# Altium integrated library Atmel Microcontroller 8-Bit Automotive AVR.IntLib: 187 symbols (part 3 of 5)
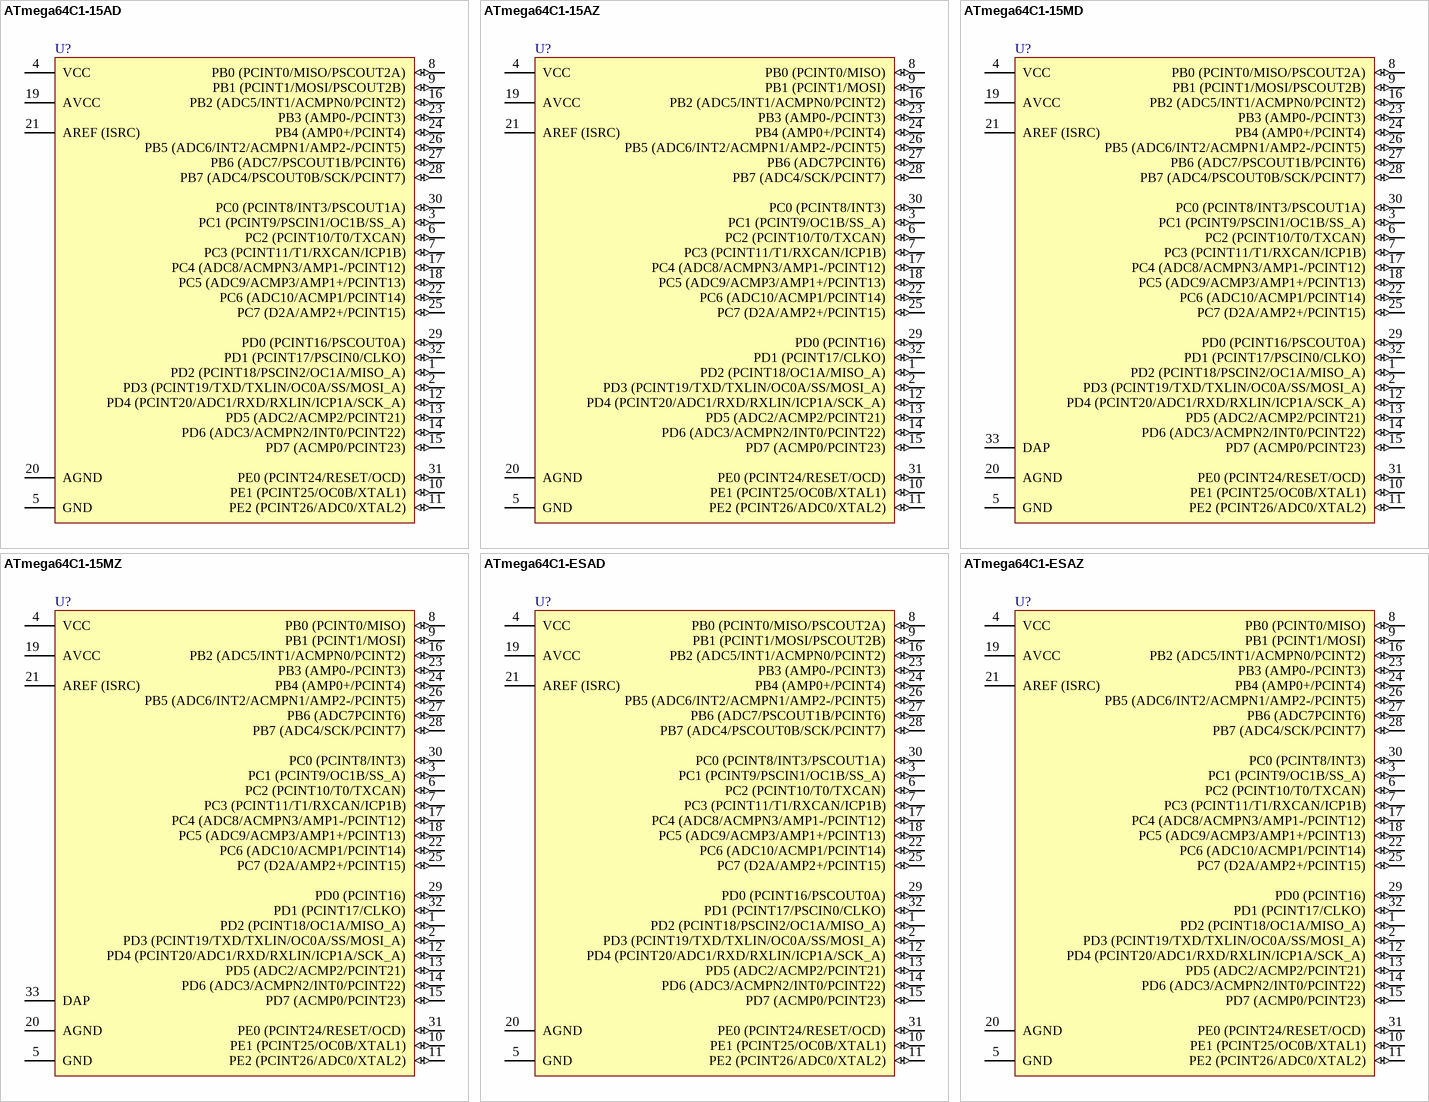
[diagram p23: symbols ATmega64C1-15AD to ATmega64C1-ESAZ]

## ATmega64C1-ESAZ
designator U?
8-bit Automotive AVR Microcontroller, 64KB Flash, 2KB EEPROM, 4KB SRAM, Engineering Sample, 32-Pin TQFP
footprint 32MA_N (Thin QFP, 32-Leads, Body 7x7mm, Pitch 0.8mm, IPC Medium Density)
footprint 32MA_L (Thin QFP, 32-Leads, Body 7x7mm, Pitch 0.8mm, IPC High Density)
footprint 32MA_M (Thin QFP, 32-Leads, Body 7x7mm, Pitch 0.8mm, IPC Low Density)
pins: 1 PD2 (PCINT18/OC1A/MISO_A) (io), 2 PD3 (PCINT19/TXD/TXLIN/OC0A/SS/MOSI_A) (io), 3 PC1 (PCINT9/OC1B/SS_A) (io), 4 VCC (power), 5 GND (power), 6 PC2 (PCINT10/T0/TXCAN) (io), 7 PC3 (PCINT11/T1/RXCAN/ICP1B) (io), 8 PB0 (PCINT0/MISO) (io), 9 PB1 (PCINT1/MOSI) (io), 10 PE1 (PCINT25/OC0B/XTAL1) (io), 11 PE2 (PCINT26/ADC0/XTAL2) (io), 12 PD4 (PCINT20/ADC1/RXD/RXLIN/ICP1A/SCK_A) (io), 13 PD5 (ADC2/ACMP2/PCINT21) (io), 14 PD6 (ADC3/ACMPN2/INT0/PCINT22) (io), 15 PD7 (ACMP0/PCINT23) (io), 16 PB2 (ADC5/INT1/ACMPN0/PCINT2) (io), 17 PC4 (ADC8/ACMPN3/AMP1-/PCINT12) (io), 18 PC5 (ADC9/ACMP3/AMP1+/PCINT13) (io), 19 AVCC (power), 20 AGND (power), 21 AREF (ISRC) (power), 22 PC6 (ADC10/ACMP1/PCINT14) (io), 23 PB3 (AMP0-/PCINT3) (io), 24 PB4 (AMP0+/PCINT4) (io), 25 PC7 (D2A/AMP2+/PCINT15) (io), 26 PB5 (ADC6/INT2/ACMPN1/AMP2-/PCINT5) (io), 27 PB6 (ADC7PCINT6) (io), 28 PB7 (ADC4/SCK/PCINT7) (io), 29 PD0 (PCINT16) (io), 30 PC0 (PCINT8/INT3) (io), 31 PE0 (PCINT24/RESET/OCD) (io), 32 PD1 (PCINT17/CLKO) (io)

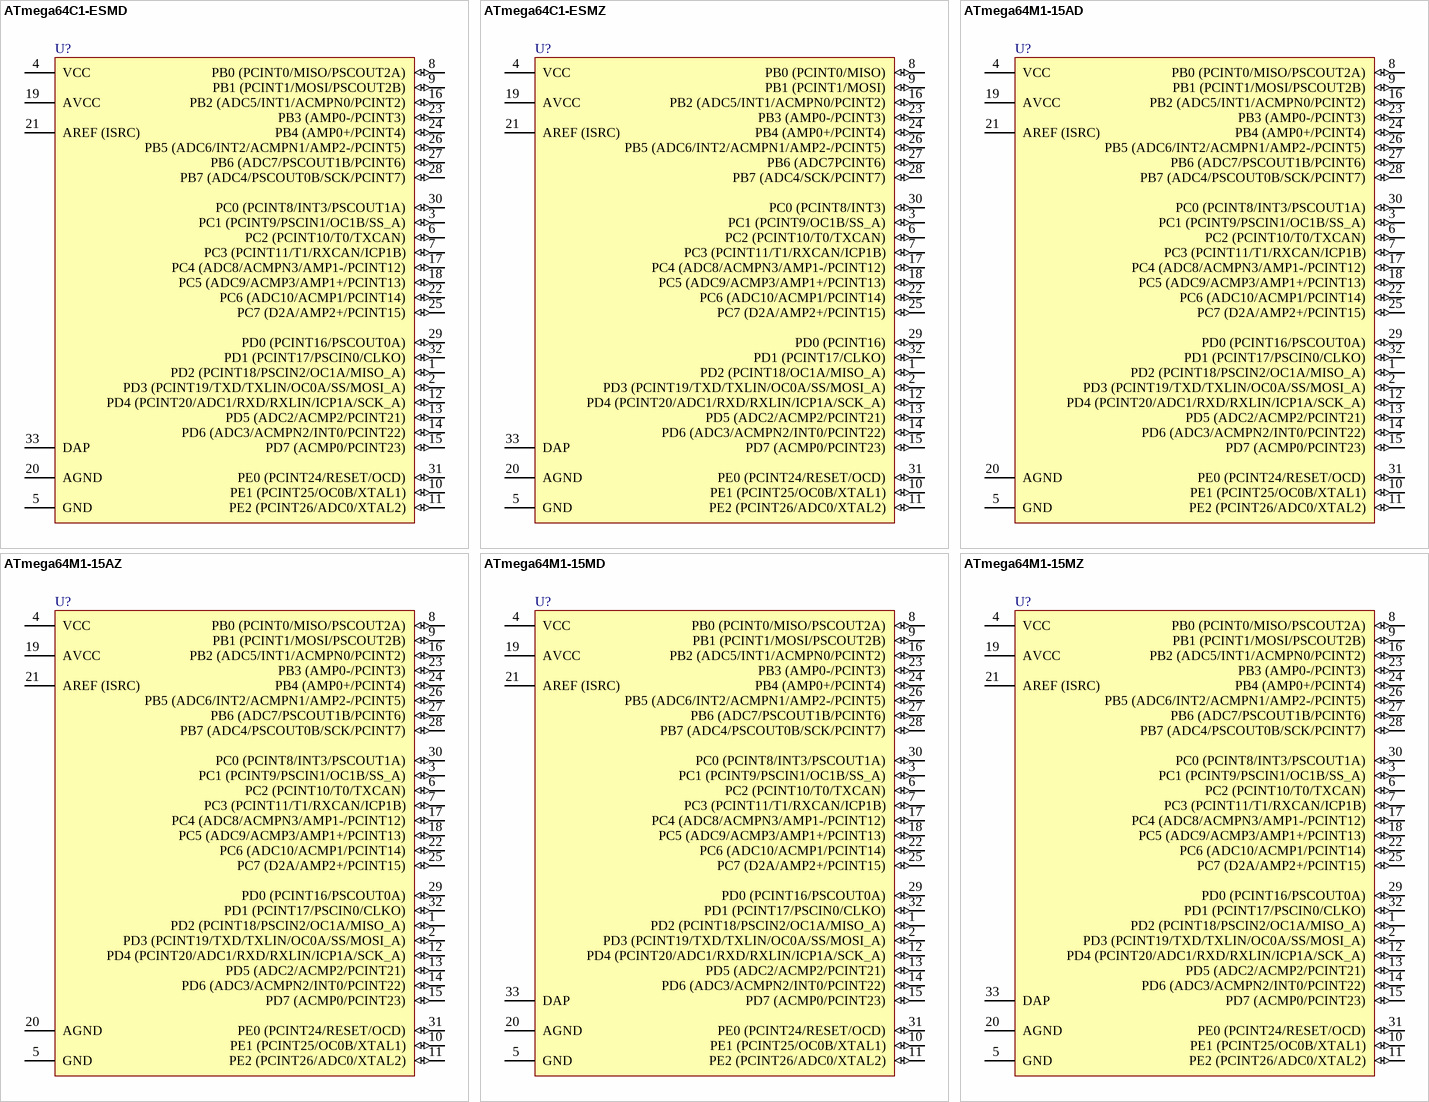
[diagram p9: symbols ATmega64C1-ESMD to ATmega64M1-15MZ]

## ATmega64C1-ESMD
designator U?
8-bit Automotive AVR Microcontroller, 64KB Flash, 2KB EEPROM, 4KB SRAM, Engineering Sample, 32-Pin VQFN
footprint 32PV_N (QFN, 32-Leads, Body 7x7 mm, Pitch 0.65mm, IPC Medium Density)
footprint 32PV_L (QFN, 32-Leads, Body 7x7 mm, Pitch 0.65mm, IPC High Density)
footprint 32PV_M (QFN, 32-Leads, Body 7x7 mm, Pitch 0.65mm, IPC Low Density)
pins: 1 PD2 (PCINT18/PSCIN2/OC1A/MISO_A) (io), 2 PD3 (PCINT19/TXD/TXLIN/OC0A/SS/MOSI_A) (io), 3 PC1 (PCINT9/PSCIN1/OC1B/SS_A) (io), 4 VCC (power), 5 GND (power), 6 PC2 (PCINT10/T0/TXCAN) (io), 7 PC3 (PCINT11/T1/RXCAN/ICP1B) (io), 8 PB0 (PCINT0/MISO/PSCOUT2A) (io), 9 PB1 (PCINT1/MOSI/PSCOUT2B) (io), 10 PE1 (PCINT25/OC0B/XTAL1) (io), 11 PE2 (PCINT26/ADC0/XTAL2) (io), 12 PD4 (PCINT20/ADC1/RXD/RXLIN/ICP1A/SCK_A) (io), 13 PD5 (ADC2/ACMP2/PCINT21) (io), 14 PD6 (ADC3/ACMPN2/INT0/PCINT22) (io), 15 PD7 (ACMP0/PCINT23) (io), 16 PB2 (ADC5/INT1/ACMPN0/PCINT2) (io), 17 PC4 (ADC8/ACMPN3/AMP1-/PCINT12) (io), 18 PC5 (ADC9/ACMP3/AMP1+/PCINT13) (io), 19 AVCC (power), 20 AGND (power), 21 AREF (ISRC) (power), 22 PC6 (ADC10/ACMP1/PCINT14) (io), 23 PB3 (AMP0-/PCINT3) (io), 24 PB4 (AMP0+/PCINT4) (io), 25 PC7 (D2A/AMP2+/PCINT15) (io), 26 PB5 (ADC6/INT2/ACMPN1/AMP2-/PCINT5) (io), 27 PB6 (ADC7/PSCOUT1B/PCINT6) (io), 28 PB7 (ADC4/PSCOUT0B/SCK/PCINT7) (io), 29 PD0 (PCINT16/PSCOUT0A) (io), 30 PC0 (PCINT8/INT3/PSCOUT1A) (io), 31 PE0 (PCINT24/RESET/OCD) (io), 32 PD1 (PCINT17/PSCIN0/CLKO) (io), 33 DAP (power)

## ATmega64C1-ESMZ
designator U?
8-bit Automotive AVR Microcontroller, 64KB Flash, 2KB EEPROM, 4KB SRAM, Engineering Sample, 32-Pin VQFN
footprint 32PV_N (QFN, 32-Leads, Body 7x7 mm, Pitch 0.65mm, IPC Medium Density)
footprint 32PV_L (QFN, 32-Leads, Body 7x7 mm, Pitch 0.65mm, IPC High Density)
footprint 32PV_M (QFN, 32-Leads, Body 7x7 mm, Pitch 0.65mm, IPC Low Density)
pins: 1 PD2 (PCINT18/OC1A/MISO_A) (io), 2 PD3 (PCINT19/TXD/TXLIN/OC0A/SS/MOSI_A) (io), 3 PC1 (PCINT9/OC1B/SS_A) (io), 4 VCC (power), 5 GND (power), 6 PC2 (PCINT10/T0/TXCAN) (io), 7 PC3 (PCINT11/T1/RXCAN/ICP1B) (io), 8 PB0 (PCINT0/MISO) (io), 9 PB1 (PCINT1/MOSI) (io), 10 PE1 (PCINT25/OC0B/XTAL1) (io), 11 PE2 (PCINT26/ADC0/XTAL2) (io), 12 PD4 (PCINT20/ADC1/RXD/RXLIN/ICP1A/SCK_A) (io), 13 PD5 (ADC2/ACMP2/PCINT21) (io), 14 PD6 (ADC3/ACMPN2/INT0/PCINT22) (io), 15 PD7 (ACMP0/PCINT23) (io), 16 PB2 (ADC5/INT1/ACMPN0/PCINT2) (io), 17 PC4 (ADC8/ACMPN3/AMP1-/PCINT12) (io), 18 PC5 (ADC9/ACMP3/AMP1+/PCINT13) (io), 19 AVCC (power), 20 AGND (power), 21 AREF (ISRC) (power), 22 PC6 (ADC10/ACMP1/PCINT14) (io), 23 PB3 (AMP0-/PCINT3) (io), 24 PB4 (AMP0+/PCINT4) (io), 25 PC7 (D2A/AMP2+/PCINT15) (io), 26 PB5 (ADC6/INT2/ACMPN1/AMP2-/PCINT5) (io), 27 PB6 (ADC7PCINT6) (io), 28 PB7 (ADC4/SCK/PCINT7) (io), 29 PD0 (PCINT16) (io), 30 PC0 (PCINT8/INT3) (io), 31 PE0 (PCINT24/RESET/OCD) (io), 32 PD1 (PCINT17/CLKO) (io), 33 DAP (power)

## ATmega64M1-15AD
designator U?
8-bit Automotive AVR Microcontroller, 64KB Flash, 2KB EEPROM, 4KB SRAM, Extended Grade (-40°C to +150°C), 32-Pin TQFP
footprint 32MA_N (Thin QFP, 32-Leads, Body 7x7mm, Pitch 0.8mm, IPC Medium Density)
footprint 32MA_L (Thin QFP, 32-Leads, Body 7x7mm, Pitch 0.8mm, IPC High Density)
footprint 32MA_M (Thin QFP, 32-Leads, Body 7x7mm, Pitch 0.8mm, IPC Low Density)
pins: 1 PD2 (PCINT18/PSCIN2/OC1A/MISO_A) (io), 2 PD3 (PCINT19/TXD/TXLIN/OC0A/SS/MOSI_A) (io), 3 PC1 (PCINT9/PSCIN1/OC1B/SS_A) (io), 4 VCC (power), 5 GND (power), 6 PC2 (PCINT10/T0/TXCAN) (io), 7 PC3 (PCINT11/T1/RXCAN/ICP1B) (io), 8 PB0 (PCINT0/MISO/PSCOUT2A) (io), 9 PB1 (PCINT1/MOSI/PSCOUT2B) (io), 10 PE1 (PCINT25/OC0B/XTAL1) (io), 11 PE2 (PCINT26/ADC0/XTAL2) (io), 12 PD4 (PCINT20/ADC1/RXD/RXLIN/ICP1A/SCK_A) (io), 13 PD5 (ADC2/ACMP2/PCINT21) (io), 14 PD6 (ADC3/ACMPN2/INT0/PCINT22) (io), 15 PD7 (ACMP0/PCINT23) (io), 16 PB2 (ADC5/INT1/ACMPN0/PCINT2) (io), 17 PC4 (ADC8/ACMPN3/AMP1-/PCINT12) (io), 18 PC5 (ADC9/ACMP3/AMP1+/PCINT13) (io), 19 AVCC (power), 20 AGND (power), 21 AREF (ISRC) (power), 22 PC6 (ADC10/ACMP1/PCINT14) (io), 23 PB3 (AMP0-/PCINT3) (io), 24 PB4 (AMP0+/PCINT4) (io), 25 PC7 (D2A/AMP2+/PCINT15) (io), 26 PB5 (ADC6/INT2/ACMPN1/AMP2-/PCINT5) (io), 27 PB6 (ADC7/PSCOUT1B/PCINT6) (io), 28 PB7 (ADC4/PSCOUT0B/SCK/PCINT7) (io), 29 PD0 (PCINT16/PSCOUT0A) (io), 30 PC0 (PCINT8/INT3/PSCOUT1A) (io), 31 PE0 (PCINT24/RESET/OCD) (io), 32 PD1 (PCINT17/PSCIN0/CLKO) (io)

## ATmega64M1-15AZ
designator U?
8-bit Automotive AVR Microcontroller, 64KB Flash, 2KB EEPROM, 4KB SRAM, PSC, Automotive Grade (-40°C to +125°C), 32-Pin TQFP
footprint 32MA_N (Thin QFP, 32-Leads, Body 7x7mm, Pitch 0.8mm, IPC Medium Density)
footprint 32MA_L (Thin QFP, 32-Leads, Body 7x7mm, Pitch 0.8mm, IPC High Density)
footprint 32MA_M (Thin QFP, 32-Leads, Body 7x7mm, Pitch 0.8mm, IPC Low Density)
pins: 1 PD2 (PCINT18/PSCIN2/OC1A/MISO_A) (io), 2 PD3 (PCINT19/TXD/TXLIN/OC0A/SS/MOSI_A) (io), 3 PC1 (PCINT9/PSCIN1/OC1B/SS_A) (io), 4 VCC (power), 5 GND (power), 6 PC2 (PCINT10/T0/TXCAN) (io), 7 PC3 (PCINT11/T1/RXCAN/ICP1B) (io), 8 PB0 (PCINT0/MISO/PSCOUT2A) (io), 9 PB1 (PCINT1/MOSI/PSCOUT2B) (io), 10 PE1 (PCINT25/OC0B/XTAL1) (io), 11 PE2 (PCINT26/ADC0/XTAL2) (io), 12 PD4 (PCINT20/ADC1/RXD/RXLIN/ICP1A/SCK_A) (io), 13 PD5 (ADC2/ACMP2/PCINT21) (io), 14 PD6 (ADC3/ACMPN2/INT0/PCINT22) (io), 15 PD7 (ACMP0/PCINT23) (io), 16 PB2 (ADC5/INT1/ACMPN0/PCINT2) (io), 17 PC4 (ADC8/ACMPN3/AMP1-/PCINT12) (io), 18 PC5 (ADC9/ACMP3/AMP1+/PCINT13) (io), 19 AVCC (power), 20 AGND (power), 21 AREF (ISRC) (power), 22 PC6 (ADC10/ACMP1/PCINT14) (io), 23 PB3 (AMP0-/PCINT3) (io), 24 PB4 (AMP0+/PCINT4) (io), 25 PC7 (D2A/AMP2+/PCINT15) (io), 26 PB5 (ADC6/INT2/ACMPN1/AMP2-/PCINT5) (io), 27 PB6 (ADC7/PSCOUT1B/PCINT6) (io), 28 PB7 (ADC4/PSCOUT0B/SCK/PCINT7) (io), 29 PD0 (PCINT16/PSCOUT0A) (io), 30 PC0 (PCINT8/INT3/PSCOUT1A) (io), 31 PE0 (PCINT24/RESET/OCD) (io), 32 PD1 (PCINT17/PSCIN0/CLKO) (io)

## ATmega64M1-15MD
designator U?
8-bit Automotive AVR Microcontroller, 64KB Flash, 2KB EEPROM, 4KB SRAM, Extended Grade (-40°C to +150°C), 32-Pin VQFN
footprint 32PV_N (QFN, 32-Leads, Body 7x7 mm, Pitch 0.65mm, IPC Medium Density)
footprint 32PV_L (QFN, 32-Leads, Body 7x7 mm, Pitch 0.65mm, IPC High Density)
footprint 32PV_M (QFN, 32-Leads, Body 7x7 mm, Pitch 0.65mm, IPC Low Density)
pins: 1 PD2 (PCINT18/PSCIN2/OC1A/MISO_A) (io), 2 PD3 (PCINT19/TXD/TXLIN/OC0A/SS/MOSI_A) (io), 3 PC1 (PCINT9/PSCIN1/OC1B/SS_A) (io), 4 VCC (power), 5 GND (power), 6 PC2 (PCINT10/T0/TXCAN) (io), 7 PC3 (PCINT11/T1/RXCAN/ICP1B) (io), 8 PB0 (PCINT0/MISO/PSCOUT2A) (io), 9 PB1 (PCINT1/MOSI/PSCOUT2B) (io), 10 PE1 (PCINT25/OC0B/XTAL1) (io), 11 PE2 (PCINT26/ADC0/XTAL2) (io), 12 PD4 (PCINT20/ADC1/RXD/RXLIN/ICP1A/SCK_A) (io), 13 PD5 (ADC2/ACMP2/PCINT21) (io), 14 PD6 (ADC3/ACMPN2/INT0/PCINT22) (io), 15 PD7 (ACMP0/PCINT23) (io), 16 PB2 (ADC5/INT1/ACMPN0/PCINT2) (io), 17 PC4 (ADC8/ACMPN3/AMP1-/PCINT12) (io), 18 PC5 (ADC9/ACMP3/AMP1+/PCINT13) (io), 19 AVCC (power), 20 AGND (power), 21 AREF (ISRC) (power), 22 PC6 (ADC10/ACMP1/PCINT14) (io), 23 PB3 (AMP0-/PCINT3) (io), 24 PB4 (AMP0+/PCINT4) (io), 25 PC7 (D2A/AMP2+/PCINT15) (io), 26 PB5 (ADC6/INT2/ACMPN1/AMP2-/PCINT5) (io), 27 PB6 (ADC7/PSCOUT1B/PCINT6) (io), 28 PB7 (ADC4/PSCOUT0B/SCK/PCINT7) (io), 29 PD0 (PCINT16/PSCOUT0A) (io), 30 PC0 (PCINT8/INT3/PSCOUT1A) (io), 31 PE0 (PCINT24/RESET/OCD) (io), 32 PD1 (PCINT17/PSCIN0/CLKO) (io), 33 DAP (power)

## ATmega64M1-15MZ
designator U?
8-bit Automotive AVR Microcontroller, 64KB Flash, 2KB EEPROM, 4KB SRAM, PSC, Automotive Grade (-40°C to +125°C), 32-Pin VQFN
footprint 32PV_N (QFN, 32-Leads, Body 7x7 mm, Pitch 0.65mm, IPC Medium Density)
footprint 32PV_L (QFN, 32-Leads, Body 7x7 mm, Pitch 0.65mm, IPC High Density)
footprint 32PV_M (QFN, 32-Leads, Body 7x7 mm, Pitch 0.65mm, IPC Low Density)
pins: 1 PD2 (PCINT18/PSCIN2/OC1A/MISO_A) (io), 2 PD3 (PCINT19/TXD/TXLIN/OC0A/SS/MOSI_A) (io), 3 PC1 (PCINT9/PSCIN1/OC1B/SS_A) (io), 4 VCC (power), 5 GND (power), 6 PC2 (PCINT10/T0/TXCAN) (io), 7 PC3 (PCINT11/T1/RXCAN/ICP1B) (io), 8 PB0 (PCINT0/MISO/PSCOUT2A) (io), 9 PB1 (PCINT1/MOSI/PSCOUT2B) (io), 10 PE1 (PCINT25/OC0B/XTAL1) (io), 11 PE2 (PCINT26/ADC0/XTAL2) (io), 12 PD4 (PCINT20/ADC1/RXD/RXLIN/ICP1A/SCK_A) (io), 13 PD5 (ADC2/ACMP2/PCINT21) (io), 14 PD6 (ADC3/ACMPN2/INT0/PCINT22) (io), 15 PD7 (ACMP0/PCINT23) (io), 16 PB2 (ADC5/INT1/ACMPN0/PCINT2) (io), 17 PC4 (ADC8/ACMPN3/AMP1-/PCINT12) (io), 18 PC5 (ADC9/ACMP3/AMP1+/PCINT13) (io), 19 AVCC (power), 20 AGND (power), 21 AREF (ISRC) (power), 22 PC6 (ADC10/ACMP1/PCINT14) (io), 23 PB3 (AMP0-/PCINT3) (io), 24 PB4 (AMP0+/PCINT4) (io), 25 PC7 (D2A/AMP2+/PCINT15) (io), 26 PB5 (ADC6/INT2/ACMPN1/AMP2-/PCINT5) (io), 27 PB6 (ADC7/PSCOUT1B/PCINT6) (io), 28 PB7 (ADC4/PSCOUT0B/SCK/PCINT7) (io), 29 PD0 (PCINT16/PSCOUT0A) (io), 30 PC0 (PCINT8/INT3/PSCOUT1A) (io), 31 PE0 (PCINT24/RESET/OCD) (io), 32 PD1 (PCINT17/PSCIN0/CLKO) (io), 33 DAP (power)

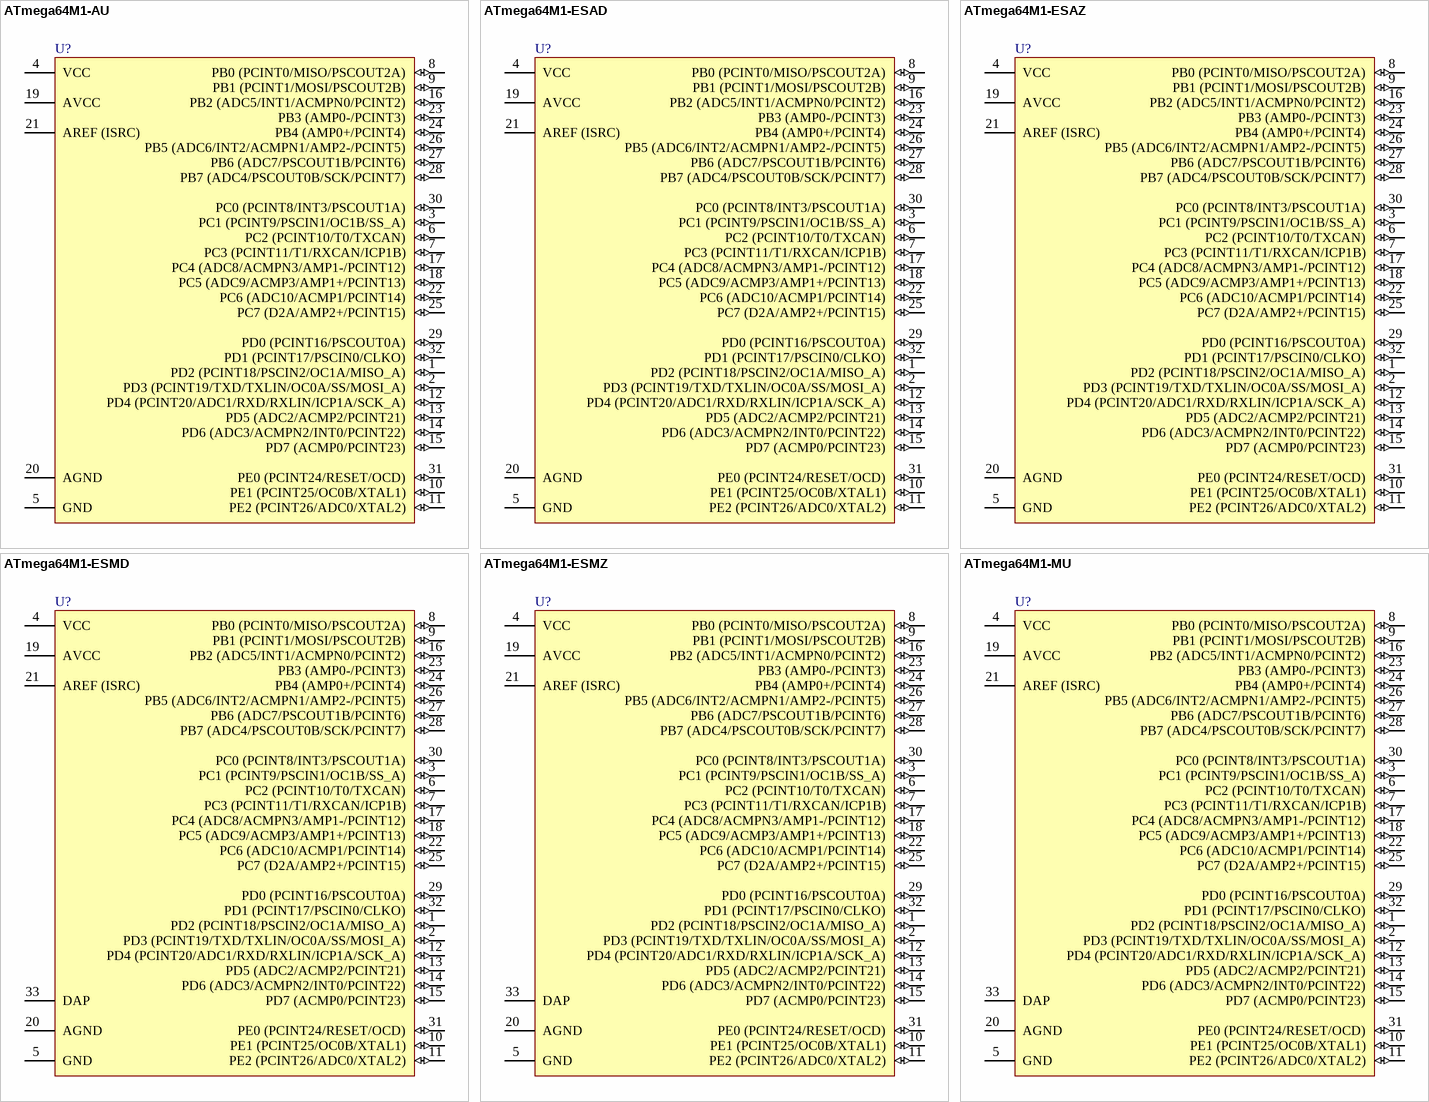
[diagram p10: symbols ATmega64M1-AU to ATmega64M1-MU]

## ATmega64M1-AU
designator U?
8-bit AVR Microcontroller, 64KB Flash, 2KB EEPROM, 4KB SRAM, Industrial Grade (-40° to +85°C), 32-Pin TQFP
footprint 32A_N (Thin QFP, 32-Leads, Body 7x7mm, Pitch 0.8mm, IPC Medium Density)
footprint 32A_L (Thin QFP, 32-Leads, Body 7x7mm, Pitch 0.8mm, IPC High Density)
footprint 32A_M (Thin QFP, 32-Leads, Body 7x7mm, Pitch 0.8mm, IPC Low Density)
pins: 1 PD2 (PCINT18/PSCIN2/OC1A/MISO_A) (io), 2 PD3 (PCINT19/TXD/TXLIN/OC0A/SS/MOSI_A) (io), 3 PC1 (PCINT9/PSCIN1/OC1B/SS_A) (io), 4 VCC (power), 5 GND (power), 6 PC2 (PCINT10/T0/TXCAN) (io), 7 PC3 (PCINT11/T1/RXCAN/ICP1B) (io), 8 PB0 (PCINT0/MISO/PSCOUT2A) (io), 9 PB1 (PCINT1/MOSI/PSCOUT2B) (io), 10 PE1 (PCINT25/OC0B/XTAL1) (io), 11 PE2 (PCINT26/ADC0/XTAL2) (io), 12 PD4 (PCINT20/ADC1/RXD/RXLIN/ICP1A/SCK_A) (io), 13 PD5 (ADC2/ACMP2/PCINT21) (io), 14 PD6 (ADC3/ACMPN2/INT0/PCINT22) (io), 15 PD7 (ACMP0/PCINT23) (io), 16 PB2 (ADC5/INT1/ACMPN0/PCINT2) (io), 17 PC4 (ADC8/ACMPN3/AMP1-/PCINT12) (io), 18 PC5 (ADC9/ACMP3/AMP1+/PCINT13) (io), 19 AVCC (power), 20 AGND (power), 21 AREF (ISRC) (power), 22 PC6 (ADC10/ACMP1/PCINT14) (io), 23 PB3 (AMP0-/PCINT3) (io), 24 PB4 (AMP0+/PCINT4) (io), 25 PC7 (D2A/AMP2+/PCINT15) (io), 26 PB5 (ADC6/INT2/ACMPN1/AMP2-/PCINT5) (io), 27 PB6 (ADC7/PSCOUT1B/PCINT6) (io), 28 PB7 (ADC4/PSCOUT0B/SCK/PCINT7) (io), 29 PD0 (PCINT16/PSCOUT0A) (io), 30 PC0 (PCINT8/INT3/PSCOUT1A) (io), 31 PE0 (PCINT24/RESET/OCD) (io), 32 PD1 (PCINT17/PSCIN0/CLKO) (io)

## ATmega64M1-ESAD
designator U?
8-bit Automotive AVR Microcontroller, 64KB Flash, 2KB EEPROM, 4KB SRAM, Engineering Sample, 32-Pin TQFP
footprint 32MA_N (Thin QFP, 32-Leads, Body 7x7mm, Pitch 0.8mm, IPC Medium Density)
footprint 32MA_L (Thin QFP, 32-Leads, Body 7x7mm, Pitch 0.8mm, IPC High Density)
footprint 32MA_M (Thin QFP, 32-Leads, Body 7x7mm, Pitch 0.8mm, IPC Low Density)
pins: 1 PD2 (PCINT18/PSCIN2/OC1A/MISO_A) (io), 2 PD3 (PCINT19/TXD/TXLIN/OC0A/SS/MOSI_A) (io), 3 PC1 (PCINT9/PSCIN1/OC1B/SS_A) (io), 4 VCC (power), 5 GND (power), 6 PC2 (PCINT10/T0/TXCAN) (io), 7 PC3 (PCINT11/T1/RXCAN/ICP1B) (io), 8 PB0 (PCINT0/MISO/PSCOUT2A) (io), 9 PB1 (PCINT1/MOSI/PSCOUT2B) (io), 10 PE1 (PCINT25/OC0B/XTAL1) (io), 11 PE2 (PCINT26/ADC0/XTAL2) (io), 12 PD4 (PCINT20/ADC1/RXD/RXLIN/ICP1A/SCK_A) (io), 13 PD5 (ADC2/ACMP2/PCINT21) (io), 14 PD6 (ADC3/ACMPN2/INT0/PCINT22) (io), 15 PD7 (ACMP0/PCINT23) (io), 16 PB2 (ADC5/INT1/ACMPN0/PCINT2) (io), 17 PC4 (ADC8/ACMPN3/AMP1-/PCINT12) (io), 18 PC5 (ADC9/ACMP3/AMP1+/PCINT13) (io), 19 AVCC (power), 20 AGND (power), 21 AREF (ISRC) (power), 22 PC6 (ADC10/ACMP1/PCINT14) (io), 23 PB3 (AMP0-/PCINT3) (io), 24 PB4 (AMP0+/PCINT4) (io), 25 PC7 (D2A/AMP2+/PCINT15) (io), 26 PB5 (ADC6/INT2/ACMPN1/AMP2-/PCINT5) (io), 27 PB6 (ADC7/PSCOUT1B/PCINT6) (io), 28 PB7 (ADC4/PSCOUT0B/SCK/PCINT7) (io), 29 PD0 (PCINT16/PSCOUT0A) (io), 30 PC0 (PCINT8/INT3/PSCOUT1A) (io), 31 PE0 (PCINT24/RESET/OCD) (io), 32 PD1 (PCINT17/PSCIN0/CLKO) (io)

## ATmega64M1-ESAZ
designator U?
8-bit Automotive AVR Microcontroller, 64KB Flash, 2KB EEPROM, 4KB SRAM, PSC, Engineering Sample, 32-Pin TQFP
footprint 32MA_N (Thin QFP, 32-Leads, Body 7x7mm, Pitch 0.8mm, IPC Medium Density)
footprint 32MA_L (Thin QFP, 32-Leads, Body 7x7mm, Pitch 0.8mm, IPC High Density)
footprint 32MA_M (Thin QFP, 32-Leads, Body 7x7mm, Pitch 0.8mm, IPC Low Density)
pins: 1 PD2 (PCINT18/PSCIN2/OC1A/MISO_A) (io), 2 PD3 (PCINT19/TXD/TXLIN/OC0A/SS/MOSI_A) (io), 3 PC1 (PCINT9/PSCIN1/OC1B/SS_A) (io), 4 VCC (power), 5 GND (power), 6 PC2 (PCINT10/T0/TXCAN) (io), 7 PC3 (PCINT11/T1/RXCAN/ICP1B) (io), 8 PB0 (PCINT0/MISO/PSCOUT2A) (io), 9 PB1 (PCINT1/MOSI/PSCOUT2B) (io), 10 PE1 (PCINT25/OC0B/XTAL1) (io), 11 PE2 (PCINT26/ADC0/XTAL2) (io), 12 PD4 (PCINT20/ADC1/RXD/RXLIN/ICP1A/SCK_A) (io), 13 PD5 (ADC2/ACMP2/PCINT21) (io), 14 PD6 (ADC3/ACMPN2/INT0/PCINT22) (io), 15 PD7 (ACMP0/PCINT23) (io), 16 PB2 (ADC5/INT1/ACMPN0/PCINT2) (io), 17 PC4 (ADC8/ACMPN3/AMP1-/PCINT12) (io), 18 PC5 (ADC9/ACMP3/AMP1+/PCINT13) (io), 19 AVCC (power), 20 AGND (power), 21 AREF (ISRC) (power), 22 PC6 (ADC10/ACMP1/PCINT14) (io), 23 PB3 (AMP0-/PCINT3) (io), 24 PB4 (AMP0+/PCINT4) (io), 25 PC7 (D2A/AMP2+/PCINT15) (io), 26 PB5 (ADC6/INT2/ACMPN1/AMP2-/PCINT5) (io), 27 PB6 (ADC7/PSCOUT1B/PCINT6) (io), 28 PB7 (ADC4/PSCOUT0B/SCK/PCINT7) (io), 29 PD0 (PCINT16/PSCOUT0A) (io), 30 PC0 (PCINT8/INT3/PSCOUT1A) (io), 31 PE0 (PCINT24/RESET/OCD) (io), 32 PD1 (PCINT17/PSCIN0/CLKO) (io)

## ATmega64M1-ESMD
designator U?
8-bit Automotive AVR Microcontroller, 64KB Flash, 2KB EEPROM, 4KB SRAM, Engineering Sample, 32-Pin VQFN
footprint 32PV_N (QFN, 32-Leads, Body 7x7 mm, Pitch 0.65mm, IPC Medium Density)
footprint 32PV_L (QFN, 32-Leads, Body 7x7 mm, Pitch 0.65mm, IPC High Density)
footprint 32PV_M (QFN, 32-Leads, Body 7x7 mm, Pitch 0.65mm, IPC Low Density)
pins: 1 PD2 (PCINT18/PSCIN2/OC1A/MISO_A) (io), 2 PD3 (PCINT19/TXD/TXLIN/OC0A/SS/MOSI_A) (io), 3 PC1 (PCINT9/PSCIN1/OC1B/SS_A) (io), 4 VCC (power), 5 GND (power), 6 PC2 (PCINT10/T0/TXCAN) (io), 7 PC3 (PCINT11/T1/RXCAN/ICP1B) (io), 8 PB0 (PCINT0/MISO/PSCOUT2A) (io), 9 PB1 (PCINT1/MOSI/PSCOUT2B) (io), 10 PE1 (PCINT25/OC0B/XTAL1) (io), 11 PE2 (PCINT26/ADC0/XTAL2) (io), 12 PD4 (PCINT20/ADC1/RXD/RXLIN/ICP1A/SCK_A) (io), 13 PD5 (ADC2/ACMP2/PCINT21) (io), 14 PD6 (ADC3/ACMPN2/INT0/PCINT22) (io), 15 PD7 (ACMP0/PCINT23) (io), 16 PB2 (ADC5/INT1/ACMPN0/PCINT2) (io), 17 PC4 (ADC8/ACMPN3/AMP1-/PCINT12) (io), 18 PC5 (ADC9/ACMP3/AMP1+/PCINT13) (io), 19 AVCC (power), 20 AGND (power), 21 AREF (ISRC) (power), 22 PC6 (ADC10/ACMP1/PCINT14) (io), 23 PB3 (AMP0-/PCINT3) (io), 24 PB4 (AMP0+/PCINT4) (io), 25 PC7 (D2A/AMP2+/PCINT15) (io), 26 PB5 (ADC6/INT2/ACMPN1/AMP2-/PCINT5) (io), 27 PB6 (ADC7/PSCOUT1B/PCINT6) (io), 28 PB7 (ADC4/PSCOUT0B/SCK/PCINT7) (io), 29 PD0 (PCINT16/PSCOUT0A) (io), 30 PC0 (PCINT8/INT3/PSCOUT1A) (io), 31 PE0 (PCINT24/RESET/OCD) (io), 32 PD1 (PCINT17/PSCIN0/CLKO) (io), 33 DAP (power)

## ATmega64M1-ESMZ
designator U?
8-bit Automotive AVR Microcontroller, 64KB Flash, 2KB EEPROM, 4KB SRAM, PSC, Engineering Sample, 32-Pin VQFN
footprint 32PV_N (QFN, 32-Leads, Body 7x7 mm, Pitch 0.65mm, IPC Medium Density)
footprint 32PV_L (QFN, 32-Leads, Body 7x7 mm, Pitch 0.65mm, IPC High Density)
footprint 32PV_M (QFN, 32-Leads, Body 7x7 mm, Pitch 0.65mm, IPC Low Density)
pins: 1 PD2 (PCINT18/PSCIN2/OC1A/MISO_A) (io), 2 PD3 (PCINT19/TXD/TXLIN/OC0A/SS/MOSI_A) (io), 3 PC1 (PCINT9/PSCIN1/OC1B/SS_A) (io), 4 VCC (power), 5 GND (power), 6 PC2 (PCINT10/T0/TXCAN) (io), 7 PC3 (PCINT11/T1/RXCAN/ICP1B) (io), 8 PB0 (PCINT0/MISO/PSCOUT2A) (io), 9 PB1 (PCINT1/MOSI/PSCOUT2B) (io), 10 PE1 (PCINT25/OC0B/XTAL1) (io), 11 PE2 (PCINT26/ADC0/XTAL2) (io), 12 PD4 (PCINT20/ADC1/RXD/RXLIN/ICP1A/SCK_A) (io), 13 PD5 (ADC2/ACMP2/PCINT21) (io), 14 PD6 (ADC3/ACMPN2/INT0/PCINT22) (io), 15 PD7 (ACMP0/PCINT23) (io), 16 PB2 (ADC5/INT1/ACMPN0/PCINT2) (io), 17 PC4 (ADC8/ACMPN3/AMP1-/PCINT12) (io), 18 PC5 (ADC9/ACMP3/AMP1+/PCINT13) (io), 19 AVCC (power), 20 AGND (power), 21 AREF (ISRC) (power), 22 PC6 (ADC10/ACMP1/PCINT14) (io), 23 PB3 (AMP0-/PCINT3) (io), 24 PB4 (AMP0+/PCINT4) (io), 25 PC7 (D2A/AMP2+/PCINT15) (io), 26 PB5 (ADC6/INT2/ACMPN1/AMP2-/PCINT5) (io), 27 PB6 (ADC7/PSCOUT1B/PCINT6) (io), 28 PB7 (ADC4/PSCOUT0B/SCK/PCINT7) (io), 29 PD0 (PCINT16/PSCOUT0A) (io), 30 PC0 (PCINT8/INT3/PSCOUT1A) (io), 31 PE0 (PCINT24/RESET/OCD) (io), 32 PD1 (PCINT17/PSCIN0/CLKO) (io), 33 DAP (power)

## ATmega64M1-MU
designator U?
8-bit AVR Microcontroller, 64KB Flash, 2KB EEPROM, 4KB SRAM, Industrial Grade (-40° to +85°C), 32-Pin MLF
footprint 32M1-A_N (QFN, 32-Leads, Body 5x5mm, Pitch 0.5mm, IPC Medium Density)
footprint 32M1-A_L (QFN, 32-Leads, Body 5x5mm, Pitch 0.5mm, IPC High Density)
footprint 32M1-A_M (QFN, 32-Leads, Body 5x5mm, Pitch 0.5mm, IPC Low Density)
pins: 1 PD2 (PCINT18/PSCIN2/OC1A/MISO_A) (io), 2 PD3 (PCINT19/TXD/TXLIN/OC0A/SS/MOSI_A) (io), 3 PC1 (PCINT9/PSCIN1/OC1B/SS_A) (io), 4 VCC (power), 5 GND (power), 6 PC2 (PCINT10/T0/TXCAN) (io), 7 PC3 (PCINT11/T1/RXCAN/ICP1B) (io), 8 PB0 (PCINT0/MISO/PSCOUT2A) (io), 9 PB1 (PCINT1/MOSI/PSCOUT2B) (io), 10 PE1 (PCINT25/OC0B/XTAL1) (io), 11 PE2 (PCINT26/ADC0/XTAL2) (io), 12 PD4 (PCINT20/ADC1/RXD/RXLIN/ICP1A/SCK_A) (io), 13 PD5 (ADC2/ACMP2/PCINT21) (io), 14 PD6 (ADC3/ACMPN2/INT0/PCINT22) (io), 15 PD7 (ACMP0/PCINT23) (io), 16 PB2 (ADC5/INT1/ACMPN0/PCINT2) (io), 17 PC4 (ADC8/ACMPN3/AMP1-/PCINT12) (io), 18 PC5 (ADC9/ACMP3/AMP1+/PCINT13) (io), 19 AVCC (power), 20 AGND (power), 21 AREF (ISRC) (power), 22 PC6 (ADC10/ACMP1/PCINT14) (io), 23 PB3 (AMP0-/PCINT3) (io), 24 PB4 (AMP0+/PCINT4) (io), 25 PC7 (D2A/AMP2+/PCINT15) (io), 26 PB5 (ADC6/INT2/ACMPN1/AMP2-/PCINT5) (io), 27 PB6 (ADC7/PSCOUT1B/PCINT6) (io), 28 PB7 (ADC4/PSCOUT0B/SCK/PCINT7) (io), 29 PD0 (PCINT16/PSCOUT0A) (io), 30 PC0 (PCINT8/INT3/PSCOUT1A) (io), 31 PE0 (PCINT24/RESET/OCD) (io), 32 PD1 (PCINT17/PSCIN0/CLKO) (io), 33 DAP (power)

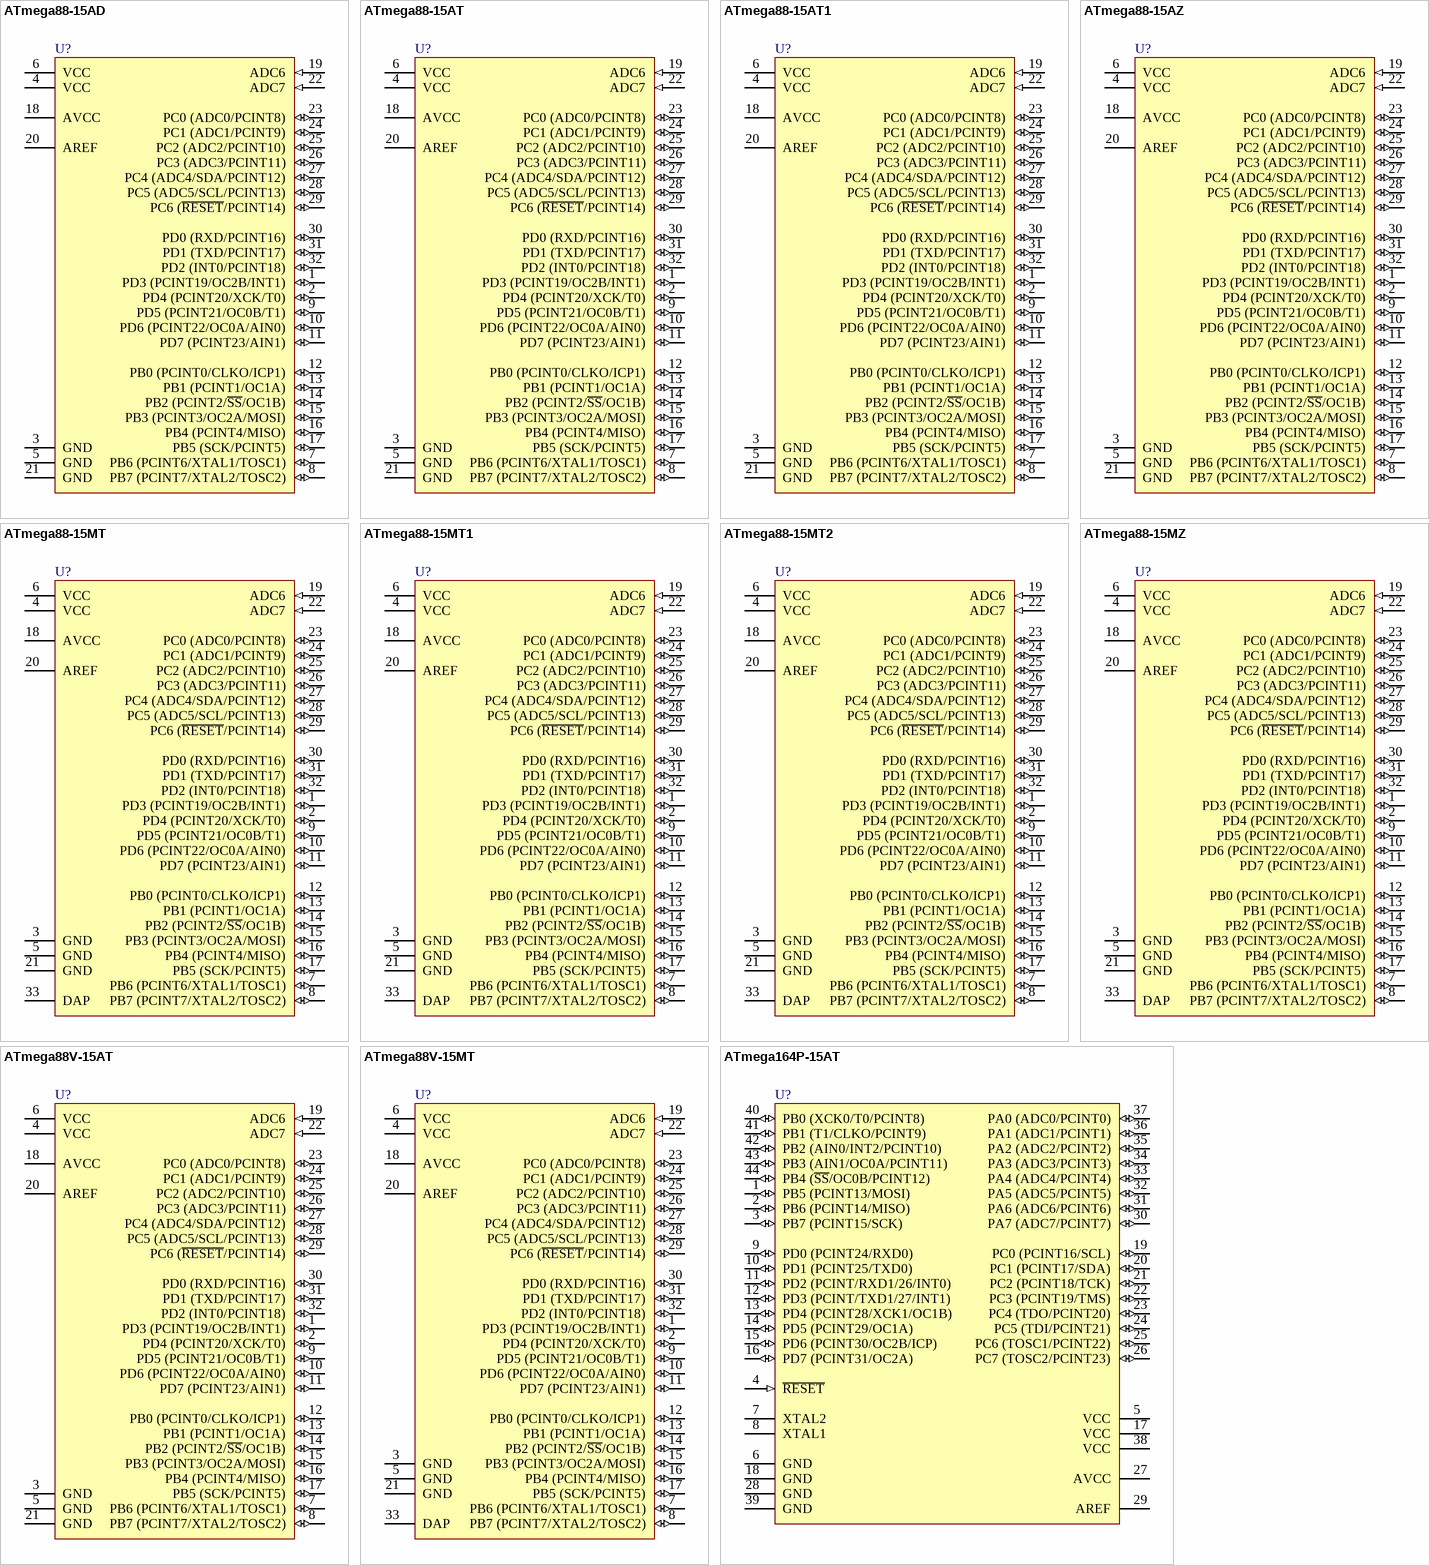
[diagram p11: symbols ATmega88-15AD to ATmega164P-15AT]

## ATmega88-15AD
designator U?
8-bit Automotive AVR Microcontroller, 8KB Flash, 512 Bytes EEPROM, 1KB SRAM, Extended Grade (-40°C to +150°C), 32-Pin TQFP
footprint 32MA_N (Thin QFP, 32-Leads, Body 7x7mm, Pitch 0.8mm, IPC Medium Density)
footprint 32MA_L (Thin QFP, 32-Leads, Body 7x7mm, Pitch 0.8mm, IPC High Density)
footprint 32MA_M (Thin QFP, 32-Leads, Body 7x7mm, Pitch 0.8mm, IPC Low Density)
pins: 1 PD3 (PCINT19/OC2B/INT1) (io), 2 PD4 (PCINT20/XCK/T0) (io), 3 GND (power), 4 VCC (power), 5 GND (power), 6 VCC (power), 7 PB6 (PCINT6/XTAL1/TOSC1) (io), 8 PB7 (PCINT7/XTAL2/TOSC2) (io), 9 PD5 (PCINT21/OC0B/T1) (io), 10 PD6 (PCINT22/OC0A/AIN0) (io), 11 PD7 (PCINT23/AIN1) (io), 12 PB0 (PCINT0/CLKO/ICP1) (io), 13 PB1 (PCINT1/OC1A) (io), 14 PB2 (PCINT2/~{SS}/OC1B) (io), 15 PB3 (PCINT3/OC2A/MOSI) (io), 16 PB4 (PCINT4/MISO) (io), 17 PB5 (SCK/PCINT5) (io), 18 AVCC (power), 19 ADC6 (in), 20 AREF, 21 GND (power), 22 ADC7 (in), 23 PC0 (ADC0/PCINT8) (io), 24 PC1 (ADC1/PCINT9) (io), 25 PC2 (ADC2/PCINT10) (io), 26 PC3 (ADC3/PCINT11) (io), 27 PC4 (ADC4/SDA/PCINT12) (io), 28 PC5 (ADC5/SCL/PCINT13) (io), 29 PC6 (~{RESET}/PCINT14) (io), 30 PD0 (RXD/PCINT16) (io), 31 PD1 (TXD/PCINT17) (io), 32 PD2 (INT0/PCINT18) (io)

## ATmega88-15AT
designator U?
8-bit Automotive AVR Microcontroller, 8KB Flash, 512 Bytes EEPROM, 1KB SRAM, Automotive Grade (-40°C to +85°C), 32-Pin TQFP
footprint 32MA_N (Thin QFP, 32-Leads, Body 7x7mm, Pitch 0.8mm, IPC Medium Density)
footprint 32MA_L (Thin QFP, 32-Leads, Body 7x7mm, Pitch 0.8mm, IPC High Density)
footprint 32MA_M (Thin QFP, 32-Leads, Body 7x7mm, Pitch 0.8mm, IPC Low Density)
pins: 1 PD3 (PCINT19/OC2B/INT1) (io), 2 PD4 (PCINT20/XCK/T0) (io), 3 GND (power), 4 VCC (power), 5 GND (power), 6 VCC (power), 7 PB6 (PCINT6/XTAL1/TOSC1) (io), 8 PB7 (PCINT7/XTAL2/TOSC2) (io), 9 PD5 (PCINT21/OC0B/T1) (io), 10 PD6 (PCINT22/OC0A/AIN0) (io), 11 PD7 (PCINT23/AIN1) (io), 12 PB0 (PCINT0/CLKO/ICP1) (io), 13 PB1 (PCINT1/OC1A) (io), 14 PB2 (PCINT2/~{SS}/OC1B) (io), 15 PB3 (PCINT3/OC2A/MOSI) (io), 16 PB4 (PCINT4/MISO) (io), 17 PB5 (SCK/PCINT5) (io), 18 AVCC (power), 19 ADC6 (in), 20 AREF, 21 GND (power), 22 ADC7 (in), 23 PC0 (ADC0/PCINT8) (io), 24 PC1 (ADC1/PCINT9) (io), 25 PC2 (ADC2/PCINT10) (io), 26 PC3 (ADC3/PCINT11) (io), 27 PC4 (ADC4/SDA/PCINT12) (io), 28 PC5 (ADC5/SCL/PCINT13) (io), 29 PC6 (~{RESET}/PCINT14) (io), 30 PD0 (RXD/PCINT16) (io), 31 PD1 (TXD/PCINT17) (io), 32 PD2 (INT0/PCINT18) (io)

## ATmega88-15AT1
designator U?
8-bit Automotive AVR Microcontroller, 8KB Flash, 512 Bytes EEPROM, 1KB SRAM, Automotive Grade (-40°C to +105°C), 32-Pin TQFP
footprint 32MA_N (Thin QFP, 32-Leads, Body 7x7mm, Pitch 0.8mm, IPC Medium Density)
footprint 32MA_L (Thin QFP, 32-Leads, Body 7x7mm, Pitch 0.8mm, IPC High Density)
footprint 32MA_M (Thin QFP, 32-Leads, Body 7x7mm, Pitch 0.8mm, IPC Low Density)
pins: 1 PD3 (PCINT19/OC2B/INT1) (io), 2 PD4 (PCINT20/XCK/T0) (io), 3 GND (power), 4 VCC (power), 5 GND (power), 6 VCC (power), 7 PB6 (PCINT6/XTAL1/TOSC1) (io), 8 PB7 (PCINT7/XTAL2/TOSC2) (io), 9 PD5 (PCINT21/OC0B/T1) (io), 10 PD6 (PCINT22/OC0A/AIN0) (io), 11 PD7 (PCINT23/AIN1) (io), 12 PB0 (PCINT0/CLKO/ICP1) (io), 13 PB1 (PCINT1/OC1A) (io), 14 PB2 (PCINT2/~{SS}/OC1B) (io), 15 PB3 (PCINT3/OC2A/MOSI) (io), 16 PB4 (PCINT4/MISO) (io), 17 PB5 (SCK/PCINT5) (io), 18 AVCC (power), 19 ADC6 (in), 20 AREF, 21 GND (power), 22 ADC7 (in), 23 PC0 (ADC0/PCINT8) (io), 24 PC1 (ADC1/PCINT9) (io), 25 PC2 (ADC2/PCINT10) (io), 26 PC3 (ADC3/PCINT11) (io), 27 PC4 (ADC4/SDA/PCINT12) (io), 28 PC5 (ADC5/SCL/PCINT13) (io), 29 PC6 (~{RESET}/PCINT14) (io), 30 PD0 (RXD/PCINT16) (io), 31 PD1 (TXD/PCINT17) (io), 32 PD2 (INT0/PCINT18) (io)

## ATmega88-15AZ
designator U?
8-bit Automotive AVR Microcontroller, 8KB Flash, 512 Bytes EEPROM, 1KB SRAM, Automotive Grade (-40°C to +125°C), 32-Pin TQFP
footprint 32MA_N (Thin QFP, 32-Leads, Body 7x7mm, Pitch 0.8mm, IPC Medium Density)
footprint 32MA_L (Thin QFP, 32-Leads, Body 7x7mm, Pitch 0.8mm, IPC High Density)
footprint 32MA_M (Thin QFP, 32-Leads, Body 7x7mm, Pitch 0.8mm, IPC Low Density)
pins: 1 PD3 (PCINT19/OC2B/INT1) (io), 2 PD4 (PCINT20/XCK/T0) (io), 3 GND (power), 4 VCC (power), 5 GND (power), 6 VCC (power), 7 PB6 (PCINT6/XTAL1/TOSC1) (io), 8 PB7 (PCINT7/XTAL2/TOSC2) (io), 9 PD5 (PCINT21/OC0B/T1) (io), 10 PD6 (PCINT22/OC0A/AIN0) (io), 11 PD7 (PCINT23/AIN1) (io), 12 PB0 (PCINT0/CLKO/ICP1) (io), 13 PB1 (PCINT1/OC1A) (io), 14 PB2 (PCINT2/~{SS}/OC1B) (io), 15 PB3 (PCINT3/OC2A/MOSI) (io), 16 PB4 (PCINT4/MISO) (io), 17 PB5 (SCK/PCINT5) (io), 18 AVCC (power), 19 ADC6 (in), 20 AREF, 21 GND (power), 22 ADC7 (in), 23 PC0 (ADC0/PCINT8) (io), 24 PC1 (ADC1/PCINT9) (io), 25 PC2 (ADC2/PCINT10) (io), 26 PC3 (ADC3/PCINT11) (io), 27 PC4 (ADC4/SDA/PCINT12) (io), 28 PC5 (ADC5/SCL/PCINT13) (io), 29 PC6 (~{RESET}/PCINT14) (io), 30 PD0 (RXD/PCINT16) (io), 31 PD1 (TXD/PCINT17) (io), 32 PD2 (INT0/PCINT18) (io)

## ATmega88-15MT
designator U?
8-bit Automotive AVR Microcontroller, 8KB Flash, 512 Bytes EEPROM, 1KB SRAM, Automotive Grade (-40°C to +85°C), 32-Pin VQFN
footprint 32PN_N (QFN, 32-Leads, Body 5x5mm, Pitch 0.5mm, IPC Medium Density)
footprint 32PN_L (QFN, 32-Leads, Body 5x5mm, Pitch 0.5mm, IPC High Density)
footprint 32PN_M (QFN, 32-Leads, Body 5x5mm, Pitch 0.5mm, IPC Low Density)
pins: 1 PD3 (PCINT19/OC2B/INT1) (io), 2 PD4 (PCINT20/XCK/T0) (io), 3 GND (power), 4 VCC (power), 5 GND (power), 6 VCC (power), 7 PB6 (PCINT6/XTAL1/TOSC1) (io), 8 PB7 (PCINT7/XTAL2/TOSC2) (io), 9 PD5 (PCINT21/OC0B/T1) (io), 10 PD6 (PCINT22/OC0A/AIN0) (io), 11 PD7 (PCINT23/AIN1) (io), 12 PB0 (PCINT0/CLKO/ICP1) (io), 13 PB1 (PCINT1/OC1A) (io), 14 PB2 (PCINT2/~{SS}/OC1B) (io), 15 PB3 (PCINT3/OC2A/MOSI) (io), 16 PB4 (PCINT4/MISO) (io), 17 PB5 (SCK/PCINT5) (io), 18 AVCC (power), 19 ADC6 (in), 20 AREF, 21 GND (power), 22 ADC7 (in), 23 PC0 (ADC0/PCINT8) (io), 24 PC1 (ADC1/PCINT9) (io), 25 PC2 (ADC2/PCINT10) (io), 26 PC3 (ADC3/PCINT11) (io), 27 PC4 (ADC4/SDA/PCINT12) (io), 28 PC5 (ADC5/SCL/PCINT13) (io), 29 PC6 (~{RESET}/PCINT14) (io), 30 PD0 (RXD/PCINT16) (io), 31 PD1 (TXD/PCINT17) (io), 32 PD2 (INT0/PCINT18) (io), 33 DAP (power)

## ATmega88-15MT1
designator U?
8-bit Automotive AVR Microcontroller, 8KB Flash, 512 Bytes EEPROM, 1KB SRAM, Automotive Grade (-40°C to +105°C), 32-Pin VQFN
footprint 32PN_N (QFN, 32-Leads, Body 5x5mm, Pitch 0.5mm, IPC Medium Density)
footprint 32PN_L (QFN, 32-Leads, Body 5x5mm, Pitch 0.5mm, IPC High Density)
footprint 32PN_M (QFN, 32-Leads, Body 5x5mm, Pitch 0.5mm, IPC Low Density)
pins: 1 PD3 (PCINT19/OC2B/INT1) (io), 2 PD4 (PCINT20/XCK/T0) (io), 3 GND (power), 4 VCC (power), 5 GND (power), 6 VCC (power), 7 PB6 (PCINT6/XTAL1/TOSC1) (io), 8 PB7 (PCINT7/XTAL2/TOSC2) (io), 9 PD5 (PCINT21/OC0B/T1) (io), 10 PD6 (PCINT22/OC0A/AIN0) (io), 11 PD7 (PCINT23/AIN1) (io), 12 PB0 (PCINT0/CLKO/ICP1) (io), 13 PB1 (PCINT1/OC1A) (io), 14 PB2 (PCINT2/~{SS}/OC1B) (io), 15 PB3 (PCINT3/OC2A/MOSI) (io), 16 PB4 (PCINT4/MISO) (io), 17 PB5 (SCK/PCINT5) (io), 18 AVCC (power), 19 ADC6 (in), 20 AREF, 21 GND (power), 22 ADC7 (in), 23 PC0 (ADC0/PCINT8) (io), 24 PC1 (ADC1/PCINT9) (io), 25 PC2 (ADC2/PCINT10) (io), 26 PC3 (ADC3/PCINT11) (io), 27 PC4 (ADC4/SDA/PCINT12) (io), 28 PC5 (ADC5/SCL/PCINT13) (io), 29 PC6 (~{RESET}/PCINT14) (io), 30 PD0 (RXD/PCINT16) (io), 31 PD1 (TXD/PCINT17) (io), 32 PD2 (INT0/PCINT18) (io), 33 DAP (power)

## ATmega88-15MT2
designator U?
8-bit Automotive AVR Microcontroller, 8KB Flash, 512 Bytes EEPROM, 1KB SRAM, Extended Grade (-40°C to +150°C), 32-Pin VQFN
footprint 32PN_N (QFN, 32-Leads, Body 5x5mm, Pitch 0.5mm, IPC Medium Density)
footprint 32PN_L (QFN, 32-Leads, Body 5x5mm, Pitch 0.5mm, IPC High Density)
footprint 32PN_M (QFN, 32-Leads, Body 5x5mm, Pitch 0.5mm, IPC Low Density)
pins: 1 PD3 (PCINT19/OC2B/INT1) (io), 2 PD4 (PCINT20/XCK/T0) (io), 3 GND (power), 4 VCC (power), 5 GND (power), 6 VCC (power), 7 PB6 (PCINT6/XTAL1/TOSC1) (io), 8 PB7 (PCINT7/XTAL2/TOSC2) (io), 9 PD5 (PCINT21/OC0B/T1) (io), 10 PD6 (PCINT22/OC0A/AIN0) (io), 11 PD7 (PCINT23/AIN1) (io), 12 PB0 (PCINT0/CLKO/ICP1) (io), 13 PB1 (PCINT1/OC1A) (io), 14 PB2 (PCINT2/~{SS}/OC1B) (io), 15 PB3 (PCINT3/OC2A/MOSI) (io), 16 PB4 (PCINT4/MISO) (io), 17 PB5 (SCK/PCINT5) (io), 18 AVCC (power), 19 ADC6 (in), 20 AREF, 21 GND (power), 22 ADC7 (in), 23 PC0 (ADC0/PCINT8) (io), 24 PC1 (ADC1/PCINT9) (io), 25 PC2 (ADC2/PCINT10) (io), 26 PC3 (ADC3/PCINT11) (io), 27 PC4 (ADC4/SDA/PCINT12) (io), 28 PC5 (ADC5/SCL/PCINT13) (io), 29 PC6 (~{RESET}/PCINT14) (io), 30 PD0 (RXD/PCINT16) (io), 31 PD1 (TXD/PCINT17) (io), 32 PD2 (INT0/PCINT18) (io), 33 DAP (power)

## ATmega88-15MZ
designator U?
8-bit Automotive AVR Microcontroller, 8KB Flash, 512 Bytes EEPROM, 1KB SRAM, Automotive Grade (-40°C to 125°C), 32-Pin VQFN
footprint 32PN_N (QFN, 32-Leads, Body 5x5mm, Pitch 0.5mm, IPC Medium Density)
footprint 32PN_L (QFN, 32-Leads, Body 5x5mm, Pitch 0.5mm, IPC High Density)
footprint 32PN_M (QFN, 32-Leads, Body 5x5mm, Pitch 0.5mm, IPC Low Density)
pins: 1 PD3 (PCINT19/OC2B/INT1) (io), 2 PD4 (PCINT20/XCK/T0) (io), 3 GND (power), 4 VCC (power), 5 GND (power), 6 VCC (power), 7 PB6 (PCINT6/XTAL1/TOSC1) (io), 8 PB7 (PCINT7/XTAL2/TOSC2) (io), 9 PD5 (PCINT21/OC0B/T1) (io), 10 PD6 (PCINT22/OC0A/AIN0) (io), 11 PD7 (PCINT23/AIN1) (io), 12 PB0 (PCINT0/CLKO/ICP1) (io), 13 PB1 (PCINT1/OC1A) (io), 14 PB2 (PCINT2/~{SS}/OC1B) (io), 15 PB3 (PCINT3/OC2A/MOSI) (io), 16 PB4 (PCINT4/MISO) (io), 17 PB5 (SCK/PCINT5) (io), 18 AVCC (power), 19 ADC6 (in), 20 AREF, 21 GND (power), 22 ADC7 (in), 23 PC0 (ADC0/PCINT8) (io), 24 PC1 (ADC1/PCINT9) (io), 25 PC2 (ADC2/PCINT10) (io), 26 PC3 (ADC3/PCINT11) (io), 27 PC4 (ADC4/SDA/PCINT12) (io), 28 PC5 (ADC5/SCL/PCINT13) (io), 29 PC6 (~{RESET}/PCINT14) (io), 30 PD0 (RXD/PCINT16) (io), 31 PD1 (TXD/PCINT17) (io), 32 PD2 (INT0/PCINT18) (io), 33 DAP (power)

## ATmega88V-15AT
designator U?
8-bit Automotive AVR Microcontroller, 1.8-5.5V, 8KB Flash, 512 Bytes EEPROM, 1KB SRAM, Automotive Grade (-40°C to +85°C), 32-Pin TQFP
footprint 32MA_N (Thin QFP, 32-Leads, Body 7x7mm, Pitch 0.8mm, IPC Medium Density)
footprint 32MA_L (Thin QFP, 32-Leads, Body 7x7mm, Pitch 0.8mm, IPC High Density)
footprint 32MA_M (Thin QFP, 32-Leads, Body 7x7mm, Pitch 0.8mm, IPC Low Density)
pins: 1 PD3 (PCINT19/OC2B/INT1) (io), 2 PD4 (PCINT20/XCK/T0) (io), 3 GND (power), 4 VCC (power), 5 GND (power), 6 VCC (power), 7 PB6 (PCINT6/XTAL1/TOSC1) (io), 8 PB7 (PCINT7/XTAL2/TOSC2) (io), 9 PD5 (PCINT21/OC0B/T1) (io), 10 PD6 (PCINT22/OC0A/AIN0) (io), 11 PD7 (PCINT23/AIN1) (io), 12 PB0 (PCINT0/CLKO/ICP1) (io), 13 PB1 (PCINT1/OC1A) (io), 14 PB2 (PCINT2/~{SS}/OC1B) (io), 15 PB3 (PCINT3/OC2A/MOSI) (io), 16 PB4 (PCINT4/MISO) (io), 17 PB5 (SCK/PCINT5) (io), 18 AVCC (power), 19 ADC6 (in), 20 AREF, 21 GND (power), 22 ADC7 (in), 23 PC0 (ADC0/PCINT8) (io), 24 PC1 (ADC1/PCINT9) (io), 25 PC2 (ADC2/PCINT10) (io), 26 PC3 (ADC3/PCINT11) (io), 27 PC4 (ADC4/SDA/PCINT12) (io), 28 PC5 (ADC5/SCL/PCINT13) (io), 29 PC6 (~{RESET}/PCINT14) (io), 30 PD0 (RXD/PCINT16) (io), 31 PD1 (TXD/PCINT17) (io), 32 PD2 (INT0/PCINT18) (io)

## ATmega88V-15MT
designator U?
8-bit Automotive AVR Microcontroller, 1.8-5.5V, 8KB Flash, 512 Bytes EEPROM, 1KB SRAM, Automotive Grade (-40°C to +85°C), 32-Pin VQFN
footprint 32PN_N (QFN, 32-Leads, Body 5x5mm, Pitch 0.5mm, IPC Medium Density)
footprint 32PN_L (QFN, 32-Leads, Body 5x5mm, Pitch 0.5mm, IPC High Density)
footprint 32PN_M (QFN, 32-Leads, Body 5x5mm, Pitch 0.5mm, IPC Low Density)
pins: 1 PD3 (PCINT19/OC2B/INT1) (io), 2 PD4 (PCINT20/XCK/T0) (io), 3 GND (power), 4 VCC (power), 5 GND (power), 6 VCC (power), 7 PB6 (PCINT6/XTAL1/TOSC1) (io), 8 PB7 (PCINT7/XTAL2/TOSC2) (io), 9 PD5 (PCINT21/OC0B/T1) (io), 10 PD6 (PCINT22/OC0A/AIN0) (io), 11 PD7 (PCINT23/AIN1) (io), 12 PB0 (PCINT0/CLKO/ICP1) (io), 13 PB1 (PCINT1/OC1A) (io), 14 PB2 (PCINT2/~{SS}/OC1B) (io), 15 PB3 (PCINT3/OC2A/MOSI) (io), 16 PB4 (PCINT4/MISO) (io), 17 PB5 (SCK/PCINT5) (io), 18 AVCC (power), 19 ADC6 (in), 20 AREF, 21 GND (power), 22 ADC7 (in), 23 PC0 (ADC0/PCINT8) (io), 24 PC1 (ADC1/PCINT9) (io), 25 PC2 (ADC2/PCINT10) (io), 26 PC3 (ADC3/PCINT11) (io), 27 PC4 (ADC4/SDA/PCINT12) (io), 28 PC5 (ADC5/SCL/PCINT13) (io), 29 PC6 (~{RESET}/PCINT14) (io), 30 PD0 (RXD/PCINT16) (io), 31 PD1 (TXD/PCINT17) (io), 32 PD2 (INT0/PCINT18) (io), 33 DAP (power)

## ATmega164P-15AT
designator U?
8-bit Automotive AVR Microcontroller, 16KB Flash, 512 Bytes EEPROM, 1KB SRAM, Automotive Quality (-40°C to +85°C), 44-Pin TQFP
footprint 44ML_N (Thin QFP, 44-Leads, Body 10x10mm, Pitch 0.8mm, IPC Medium Density)
footprint 44ML_L (Thin QFP, 44-Leads, Body 10x10mm, Pitch 0.8mm, IPC High Density)
footprint 44ML_M (Thin QFP, 44-Leads, Body 10x10mm, Pitch 0.8mm, IPC Low Density)
pins: 1 PB5 (PCINT13/MOSI) (io), 2 PB6 (PCINT14/MISO) (io), 3 PB7 (PCINT15/SCK) (io), 4 ~{RESET} (in), 5 VCC (power), 6 GND (power), 7 XTAL2, 8 XTAL1, 9 PD0 (PCINT24/RXD0) (io), 10 PD1 (PCINT25/TXD0) (io), 11 PD2 (PCINT/RXD1/26/INT0) (io), 12 PD3 (PCINT/TXD1/27/INT1) (io), 13 PD4 (PCINT28/XCK1/OC1B) (io), 14 PD5 (PCINT29/OC1A) (io), 15 PD6 (PCINT30/OC2B/ICP) (io), 16 PD7 (PCINT31/OC2A) (io), 17 VCC (power), 18 GND (power), 19 PC0 (PCINT16/SCL) (io), 20 PC1 (PCINT17/SDA) (io), 21 PC2 (PCINT18/TCK) (io), 22 PC3 (PCINT19/TMS) (io), 23 PC4 (TDO/PCINT20) (io), 24 PC5 (TDI/PCINT21) (io), 25 PC6 (TOSC1/PCINT22) (io), 26 PC7 (TOSC2/PCINT23) (io), 27 AVCC (power), 28 GND (power), 29 AREF (power), 30 PA7 (ADC7/PCINT7) (io), 31 PA6 (ADC6/PCINT6) (io), 32 PA5 (ADC5/PCINT5) (io), 33 PA4 (ADC4/PCINT4) (io), 34 PA3 (ADC3/PCINT3) (io), 35 PA2 (ADC2/PCINT2) (io), 36 PA1 (ADC1/PCINT1) (io), 37 PA0 (ADC0/PCINT0) (io), 38 VCC (power), 39 GND (power), 40 PB0 (XCK0/T0/PCINT8) (io), 41 PB1 (T1/CLKO/PCINT9) (io), 42 PB2 (AIN0/INT2/PCINT10) (io), 43 PB3 (AIN1/OC0A/PCINT11) (io), 44 PB4 (~{SS}/OC0B/PCINT12) (io)

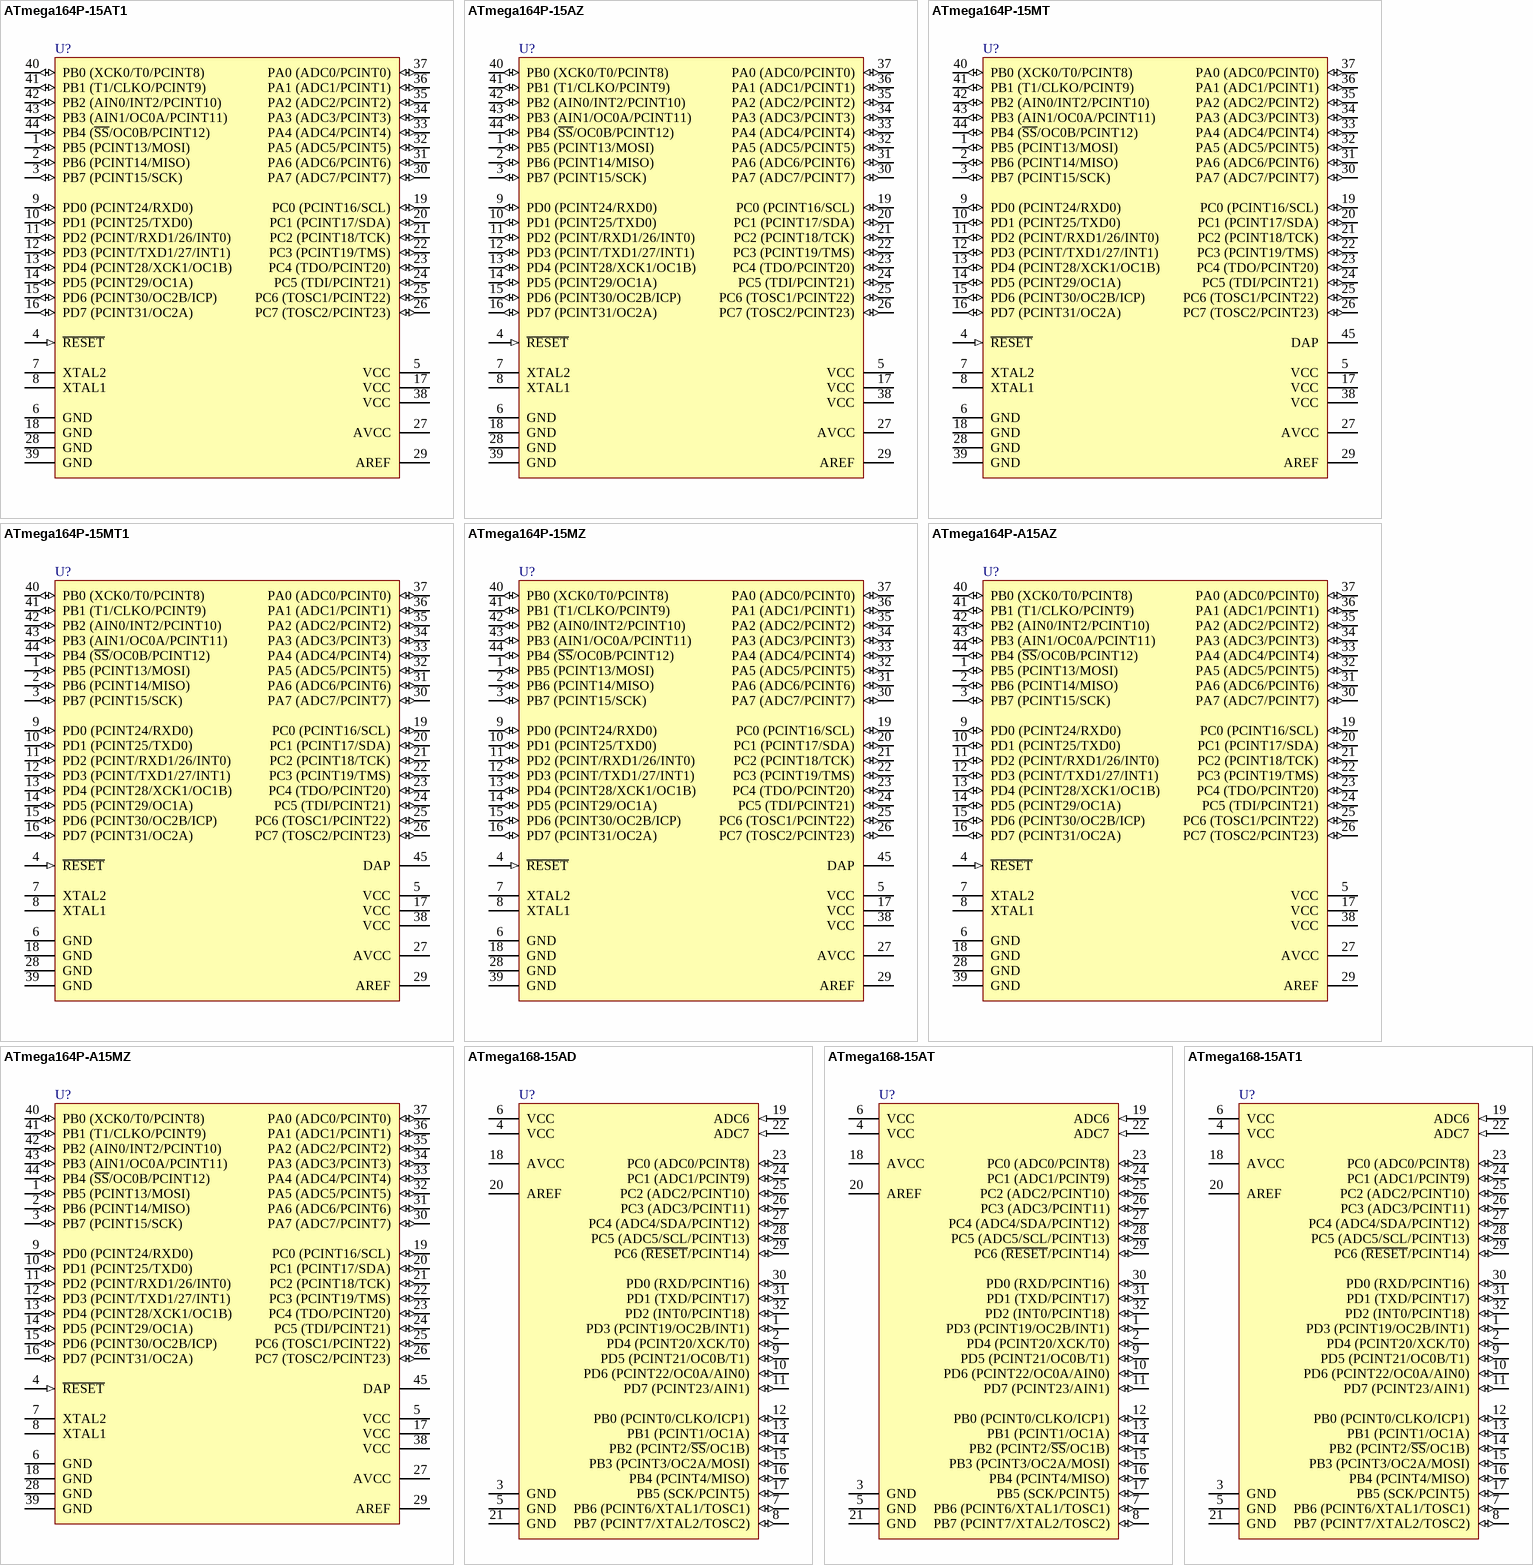
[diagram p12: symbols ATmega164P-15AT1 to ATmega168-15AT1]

## ATmega164P-15AT1
designator U?
8-bit Automotive AVR Microcontroller, 16KB Flash, 512 Bytes EEPROM, 1KB SRAM, Reduced Automotive Grade (-40°C to +105°C), 44-Pin TQFP
footprint 44ML_N (Thin QFP, 44-Leads, Body 10x10mm, Pitch 0.8mm, IPC Medium Density)
footprint 44ML_L (Thin QFP, 44-Leads, Body 10x10mm, Pitch 0.8mm, IPC High Density)
footprint 44ML_M (Thin QFP, 44-Leads, Body 10x10mm, Pitch 0.8mm, IPC Low Density)
pins: 1 PB5 (PCINT13/MOSI) (io), 2 PB6 (PCINT14/MISO) (io), 3 PB7 (PCINT15/SCK) (io), 4 ~{RESET} (in), 5 VCC (power), 6 GND (power), 7 XTAL2, 8 XTAL1, 9 PD0 (PCINT24/RXD0) (io), 10 PD1 (PCINT25/TXD0) (io), 11 PD2 (PCINT/RXD1/26/INT0) (io), 12 PD3 (PCINT/TXD1/27/INT1) (io), 13 PD4 (PCINT28/XCK1/OC1B) (io), 14 PD5 (PCINT29/OC1A) (io), 15 PD6 (PCINT30/OC2B/ICP) (io), 16 PD7 (PCINT31/OC2A) (io), 17 VCC (power), 18 GND (power), 19 PC0 (PCINT16/SCL) (io), 20 PC1 (PCINT17/SDA) (io), 21 PC2 (PCINT18/TCK) (io), 22 PC3 (PCINT19/TMS) (io), 23 PC4 (TDO/PCINT20) (io), 24 PC5 (TDI/PCINT21) (io), 25 PC6 (TOSC1/PCINT22) (io), 26 PC7 (TOSC2/PCINT23) (io), 27 AVCC (power), 28 GND (power), 29 AREF (power), 30 PA7 (ADC7/PCINT7) (io), 31 PA6 (ADC6/PCINT6) (io), 32 PA5 (ADC5/PCINT5) (io), 33 PA4 (ADC4/PCINT4) (io), 34 PA3 (ADC3/PCINT3) (io), 35 PA2 (ADC2/PCINT2) (io), 36 PA1 (ADC1/PCINT1) (io), 37 PA0 (ADC0/PCINT0) (io), 38 VCC (power), 39 GND (power), 40 PB0 (XCK0/T0/PCINT8) (io), 41 PB1 (T1/CLKO/PCINT9) (io), 42 PB2 (AIN0/INT2/PCINT10) (io), 43 PB3 (AIN1/OC0A/PCINT11) (io), 44 PB4 (~{SS}/OC0B/PCINT12) (io)

## ATmega164P-15AZ
designator U?
8-bit Automotive AVR Microcontroller, 16KB Flash, 512 Bytes EEPROM, 1KB SRAM, Automotive Grade (-40°C to +125°C), 44-Pin TQFP
footprint 44ML_N (Thin QFP, 44-Leads, Body 10x10mm, Pitch 0.8mm, IPC Medium Density)
footprint 44ML_L (Thin QFP, 44-Leads, Body 10x10mm, Pitch 0.8mm, IPC High Density)
footprint 44ML_M (Thin QFP, 44-Leads, Body 10x10mm, Pitch 0.8mm, IPC Low Density)
pins: 1 PB5 (PCINT13/MOSI) (io), 2 PB6 (PCINT14/MISO) (io), 3 PB7 (PCINT15/SCK) (io), 4 ~{RESET} (in), 5 VCC (power), 6 GND (power), 7 XTAL2, 8 XTAL1, 9 PD0 (PCINT24/RXD0) (io), 10 PD1 (PCINT25/TXD0) (io), 11 PD2 (PCINT/RXD1/26/INT0) (io), 12 PD3 (PCINT/TXD1/27/INT1) (io), 13 PD4 (PCINT28/XCK1/OC1B) (io), 14 PD5 (PCINT29/OC1A) (io), 15 PD6 (PCINT30/OC2B/ICP) (io), 16 PD7 (PCINT31/OC2A) (io), 17 VCC (power), 18 GND (power), 19 PC0 (PCINT16/SCL) (io), 20 PC1 (PCINT17/SDA) (io), 21 PC2 (PCINT18/TCK) (io), 22 PC3 (PCINT19/TMS) (io), 23 PC4 (TDO/PCINT20) (io), 24 PC5 (TDI/PCINT21) (io), 25 PC6 (TOSC1/PCINT22) (io), 26 PC7 (TOSC2/PCINT23) (io), 27 AVCC (power), 28 GND (power), 29 AREF (power), 30 PA7 (ADC7/PCINT7) (io), 31 PA6 (ADC6/PCINT6) (io), 32 PA5 (ADC5/PCINT5) (io), 33 PA4 (ADC4/PCINT4) (io), 34 PA3 (ADC3/PCINT3) (io), 35 PA2 (ADC2/PCINT2) (io), 36 PA1 (ADC1/PCINT1) (io), 37 PA0 (ADC0/PCINT0) (io), 38 VCC (power), 39 GND (power), 40 PB0 (XCK0/T0/PCINT8) (io), 41 PB1 (T1/CLKO/PCINT9) (io), 42 PB2 (AIN0/INT2/PCINT10) (io), 43 PB3 (AIN1/OC0A/PCINT11) (io), 44 PB4 (~{SS}/OC0B/PCINT12) (io)

## ATmega164P-15MT
designator U?
8-bit Automotive AVR Microcontroller, 16KB Flash, 512 Bytes EEPROM, 1KB SRAM, Automotive Quality (-40°C to +85°C), 44-Pin VQFN
footprint 44PW_N (QFN, 44-Leads, Body 7x7mm, Pitch 0.5mm, IPC Medium Density)
footprint 44PW_L (QFN, 44-Leads, Body 7x7mm, Pitch 0.5mm, IPC High Density)
footprint 44PW_M (QFN, 44-Leads, Body 7x7mm, Pitch 0.5mm, IPC Low Density)
pins: 1 PB5 (PCINT13/MOSI) (io), 2 PB6 (PCINT14/MISO) (io), 3 PB7 (PCINT15/SCK) (io), 4 ~{RESET} (in), 5 VCC (power), 6 GND (power), 7 XTAL2, 8 XTAL1, 9 PD0 (PCINT24/RXD0) (io), 10 PD1 (PCINT25/TXD0) (io), 11 PD2 (PCINT/RXD1/26/INT0) (io), 12 PD3 (PCINT/TXD1/27/INT1) (io), 13 PD4 (PCINT28/XCK1/OC1B) (io), 14 PD5 (PCINT29/OC1A) (io), 15 PD6 (PCINT30/OC2B/ICP) (io), 16 PD7 (PCINT31/OC2A) (io), 17 VCC (power), 18 GND (power), 19 PC0 (PCINT16/SCL) (io), 20 PC1 (PCINT17/SDA) (io), 21 PC2 (PCINT18/TCK) (io), 22 PC3 (PCINT19/TMS) (io), 23 PC4 (TDO/PCINT20) (io), 24 PC5 (TDI/PCINT21) (io), 25 PC6 (TOSC1/PCINT22) (io), 26 PC7 (TOSC2/PCINT23) (io), 27 AVCC (power), 28 GND (power), 29 AREF, 30 PA7 (ADC7/PCINT7) (io), 31 PA6 (ADC6/PCINT6) (io), 32 PA5 (ADC5/PCINT5) (io), 33 PA4 (ADC4/PCINT4) (io), 34 PA3 (ADC3/PCINT3) (io), 35 PA2 (ADC2/PCINT2) (io), 36 PA1 (ADC1/PCINT1) (io), 37 PA0 (ADC0/PCINT0) (io), 38 VCC (power), 39 GND (power), 40 PB0 (XCK0/T0/PCINT8) (io), 41 PB1 (T1/CLKO/PCINT9) (io), 42 PB2 (AIN0/INT2/PCINT10) (io), 43 PB3 (AIN1/OC0A/PCINT11) (io), 44 PB4 (~{SS}/OC0B/PCINT12) (io), 45 DAP (power)

## ATmega164P-15MT1
designator U?
8-bit Automotive AVR Microcontroller, 16KB Flash, 512 Bytes EEPROM, 1KB SRAM, Reduced Automotive Grade (-40°C to +105°C), 44-Pin VQFN
footprint 44PW_N (QFN, 44-Leads, Body 7x7mm, Pitch 0.5mm, IPC Medium Density)
footprint 44PW_L (QFN, 44-Leads, Body 7x7mm, Pitch 0.5mm, IPC High Density)
footprint 44PW_M (QFN, 44-Leads, Body 7x7mm, Pitch 0.5mm, IPC Low Density)
pins: 1 PB5 (PCINT13/MOSI) (io), 2 PB6 (PCINT14/MISO) (io), 3 PB7 (PCINT15/SCK) (io), 4 ~{RESET} (in), 5 VCC (power), 6 GND (power), 7 XTAL2, 8 XTAL1, 9 PD0 (PCINT24/RXD0) (io), 10 PD1 (PCINT25/TXD0) (io), 11 PD2 (PCINT/RXD1/26/INT0) (io), 12 PD3 (PCINT/TXD1/27/INT1) (io), 13 PD4 (PCINT28/XCK1/OC1B) (io), 14 PD5 (PCINT29/OC1A) (io), 15 PD6 (PCINT30/OC2B/ICP) (io), 16 PD7 (PCINT31/OC2A) (io), 17 VCC (power), 18 GND (power), 19 PC0 (PCINT16/SCL) (io), 20 PC1 (PCINT17/SDA) (io), 21 PC2 (PCINT18/TCK) (io), 22 PC3 (PCINT19/TMS) (io), 23 PC4 (TDO/PCINT20) (io), 24 PC5 (TDI/PCINT21) (io), 25 PC6 (TOSC1/PCINT22) (io), 26 PC7 (TOSC2/PCINT23) (io), 27 AVCC (power), 28 GND (power), 29 AREF, 30 PA7 (ADC7/PCINT7) (io), 31 PA6 (ADC6/PCINT6) (io), 32 PA5 (ADC5/PCINT5) (io), 33 PA4 (ADC4/PCINT4) (io), 34 PA3 (ADC3/PCINT3) (io), 35 PA2 (ADC2/PCINT2) (io), 36 PA1 (ADC1/PCINT1) (io), 37 PA0 (ADC0/PCINT0) (io), 38 VCC (power), 39 GND (power), 40 PB0 (XCK0/T0/PCINT8) (io), 41 PB1 (T1/CLKO/PCINT9) (io), 42 PB2 (AIN0/INT2/PCINT10) (io), 43 PB3 (AIN1/OC0A/PCINT11) (io), 44 PB4 (~{SS}/OC0B/PCINT12) (io), 45 DAP (power)

## ATmega164P-15MZ
designator U?
8-bit Automotive AVR Microcontroller, 16KB Flash, 512 Bytes EEPROM, 1KB SRAM, Automotive Grade (-40°C to +125°C), 44-Pin VQFN
footprint 44PW_N (QFN, 44-Leads, Body 7x7mm, Pitch 0.5mm, IPC Medium Density)
footprint 44PW_L (QFN, 44-Leads, Body 7x7mm, Pitch 0.5mm, IPC High Density)
footprint 44PW_M (QFN, 44-Leads, Body 7x7mm, Pitch 0.5mm, IPC Low Density)
pins: 1 PB5 (PCINT13/MOSI) (io), 2 PB6 (PCINT14/MISO) (io), 3 PB7 (PCINT15/SCK) (io), 4 ~{RESET} (in), 5 VCC (power), 6 GND (power), 7 XTAL2, 8 XTAL1, 9 PD0 (PCINT24/RXD0) (io), 10 PD1 (PCINT25/TXD0) (io), 11 PD2 (PCINT/RXD1/26/INT0) (io), 12 PD3 (PCINT/TXD1/27/INT1) (io), 13 PD4 (PCINT28/XCK1/OC1B) (io), 14 PD5 (PCINT29/OC1A) (io), 15 PD6 (PCINT30/OC2B/ICP) (io), 16 PD7 (PCINT31/OC2A) (io), 17 VCC (power), 18 GND (power), 19 PC0 (PCINT16/SCL) (io), 20 PC1 (PCINT17/SDA) (io), 21 PC2 (PCINT18/TCK) (io), 22 PC3 (PCINT19/TMS) (io), 23 PC4 (TDO/PCINT20) (io), 24 PC5 (TDI/PCINT21) (io), 25 PC6 (TOSC1/PCINT22) (io), 26 PC7 (TOSC2/PCINT23) (io), 27 AVCC (power), 28 GND (power), 29 AREF, 30 PA7 (ADC7/PCINT7) (io), 31 PA6 (ADC6/PCINT6) (io), 32 PA5 (ADC5/PCINT5) (io), 33 PA4 (ADC4/PCINT4) (io), 34 PA3 (ADC3/PCINT3) (io), 35 PA2 (ADC2/PCINT2) (io), 36 PA1 (ADC1/PCINT1) (io), 37 PA0 (ADC0/PCINT0) (io), 38 VCC (power), 39 GND (power), 40 PB0 (XCK0/T0/PCINT8) (io), 41 PB1 (T1/CLKO/PCINT9) (io), 42 PB2 (AIN0/INT2/PCINT10) (io), 43 PB3 (AIN1/OC0A/PCINT11) (io), 44 PB4 (~{SS}/OC0B/PCINT12) (io), 45 DAP (power)

## ATmega164P-A15AZ
designator U?
8-bit Automotive AVR Microcontroller, 16KB Flash, 512 Bytes EEPROM, 1KB SRAM, Automotive Grade (-40°C to +125°C), 44-Pin TQFP
footprint 44ML_N (Thin QFP, 44-Leads, Body 10x10mm, Pitch 0.8mm, IPC Medium Density)
footprint 44ML_L (Thin QFP, 44-Leads, Body 10x10mm, Pitch 0.8mm, IPC High Density)
footprint 44ML_M (Thin QFP, 44-Leads, Body 10x10mm, Pitch 0.8mm, IPC Low Density)
pins: 1 PB5 (PCINT13/MOSI) (io), 2 PB6 (PCINT14/MISO) (io), 3 PB7 (PCINT15/SCK) (io), 4 ~{RESET} (in), 5 VCC (power), 6 GND (power), 7 XTAL2, 8 XTAL1, 9 PD0 (PCINT24/RXD0) (io), 10 PD1 (PCINT25/TXD0) (io), 11 PD2 (PCINT/RXD1/26/INT0) (io), 12 PD3 (PCINT/TXD1/27/INT1) (io), 13 PD4 (PCINT28/XCK1/OC1B) (io), 14 PD5 (PCINT29/OC1A) (io), 15 PD6 (PCINT30/OC2B/ICP) (io), 16 PD7 (PCINT31/OC2A) (io), 17 VCC (power), 18 GND (power), 19 PC0 (PCINT16/SCL) (io), 20 PC1 (PCINT17/SDA) (io), 21 PC2 (PCINT18/TCK) (io), 22 PC3 (PCINT19/TMS) (io), 23 PC4 (TDO/PCINT20) (io), 24 PC5 (TDI/PCINT21) (io), 25 PC6 (TOSC1/PCINT22) (io), 26 PC7 (TOSC2/PCINT23) (io), 27 AVCC (power), 28 GND (power), 29 AREF (power), 30 PA7 (ADC7/PCINT7) (io), 31 PA6 (ADC6/PCINT6) (io), 32 PA5 (ADC5/PCINT5) (io), 33 PA4 (ADC4/PCINT4) (io), 34 PA3 (ADC3/PCINT3) (io), 35 PA2 (ADC2/PCINT2) (io), 36 PA1 (ADC1/PCINT1) (io), 37 PA0 (ADC0/PCINT0) (io), 38 VCC (power), 39 GND (power), 40 PB0 (XCK0/T0/PCINT8) (io), 41 PB1 (T1/CLKO/PCINT9) (io), 42 PB2 (AIN0/INT2/PCINT10) (io), 43 PB3 (AIN1/OC0A/PCINT11) (io), 44 PB4 (~{SS}/OC0B/PCINT12) (io)

## ATmega164P-A15MZ
designator U?
8-bit Automotive AVR Microcontroller, 16KB Flash, 512 Bytes EEPROM, 1KB SRAM, Automotive Grade (-40°C to +125°C), 44-Pin VQFN
footprint 44PW_N (QFN, 44-Leads, Body 7x7mm, Pitch 0.5mm, IPC Medium Density)
footprint 44PW_L (QFN, 44-Leads, Body 7x7mm, Pitch 0.5mm, IPC High Density)
footprint 44PW_M (QFN, 44-Leads, Body 7x7mm, Pitch 0.5mm, IPC Low Density)
pins: 1 PB5 (PCINT13/MOSI) (io), 2 PB6 (PCINT14/MISO) (io), 3 PB7 (PCINT15/SCK) (io), 4 ~{RESET} (in), 5 VCC (power), 6 GND (power), 7 XTAL2, 8 XTAL1, 9 PD0 (PCINT24/RXD0) (io), 10 PD1 (PCINT25/TXD0) (io), 11 PD2 (PCINT/RXD1/26/INT0) (io), 12 PD3 (PCINT/TXD1/27/INT1) (io), 13 PD4 (PCINT28/XCK1/OC1B) (io), 14 PD5 (PCINT29/OC1A) (io), 15 PD6 (PCINT30/OC2B/ICP) (io), 16 PD7 (PCINT31/OC2A) (io), 17 VCC (power), 18 GND (power), 19 PC0 (PCINT16/SCL) (io), 20 PC1 (PCINT17/SDA) (io), 21 PC2 (PCINT18/TCK) (io), 22 PC3 (PCINT19/TMS) (io), 23 PC4 (TDO/PCINT20) (io), 24 PC5 (TDI/PCINT21) (io), 25 PC6 (TOSC1/PCINT22) (io), 26 PC7 (TOSC2/PCINT23) (io), 27 AVCC (power), 28 GND (power), 29 AREF, 30 PA7 (ADC7/PCINT7) (io), 31 PA6 (ADC6/PCINT6) (io), 32 PA5 (ADC5/PCINT5) (io), 33 PA4 (ADC4/PCINT4) (io), 34 PA3 (ADC3/PCINT3) (io), 35 PA2 (ADC2/PCINT2) (io), 36 PA1 (ADC1/PCINT1) (io), 37 PA0 (ADC0/PCINT0) (io), 38 VCC (power), 39 GND (power), 40 PB0 (XCK0/T0/PCINT8) (io), 41 PB1 (T1/CLKO/PCINT9) (io), 42 PB2 (AIN0/INT2/PCINT10) (io), 43 PB3 (AIN1/OC0A/PCINT11) (io), 44 PB4 (~{SS}/OC0B/PCINT12) (io), 45 DAP (power)

## ATmega168-15AD
designator U?
8-bit Automotive AVR Microcontroller, 16KB Flash, 512 Bytes EEPROM, 1KB SRAM, Extended Grade (-40°C to +150°C), 32-Pin TQFP
footprint 32MA_N (Thin QFP, 32-Leads, Body 7x7mm, Pitch 0.8mm, IPC Medium Density)
footprint 32MA_L (Thin QFP, 32-Leads, Body 7x7mm, Pitch 0.8mm, IPC High Density)
footprint 32MA_M (Thin QFP, 32-Leads, Body 7x7mm, Pitch 0.8mm, IPC Low Density)
pins: 1 PD3 (PCINT19/OC2B/INT1) (io), 2 PD4 (PCINT20/XCK/T0) (io), 3 GND (power), 4 VCC (power), 5 GND (power), 6 VCC (power), 7 PB6 (PCINT6/XTAL1/TOSC1) (io), 8 PB7 (PCINT7/XTAL2/TOSC2) (io), 9 PD5 (PCINT21/OC0B/T1) (io), 10 PD6 (PCINT22/OC0A/AIN0) (io), 11 PD7 (PCINT23/AIN1) (io), 12 PB0 (PCINT0/CLKO/ICP1) (io), 13 PB1 (PCINT1/OC1A) (io), 14 PB2 (PCINT2/~{SS}/OC1B) (io), 15 PB3 (PCINT3/OC2A/MOSI) (io), 16 PB4 (PCINT4/MISO) (io), 17 PB5 (SCK/PCINT5) (io), 18 AVCC (power), 19 ADC6 (in), 20 AREF, 21 GND (power), 22 ADC7 (in), 23 PC0 (ADC0/PCINT8) (io), 24 PC1 (ADC1/PCINT9) (io), 25 PC2 (ADC2/PCINT10) (io), 26 PC3 (ADC3/PCINT11) (io), 27 PC4 (ADC4/SDA/PCINT12) (io), 28 PC5 (ADC5/SCL/PCINT13) (io), 29 PC6 (~{RESET}/PCINT14) (io), 30 PD0 (RXD/PCINT16) (io), 31 PD1 (TXD/PCINT17) (io), 32 PD2 (INT0/PCINT18) (io)

## ATmega168-15AT
designator U?
8-bit Automotive AVR Microcontroller, 16KB Flash, 512 Bytes EEPROM, 1KB SRAM, Automotive Grade (-40°C to +85°C), 32-Pin TQFP
footprint 32MA_N (Thin QFP, 32-Leads, Body 7x7mm, Pitch 0.8mm, IPC Medium Density)
footprint 32MA_L (Thin QFP, 32-Leads, Body 7x7mm, Pitch 0.8mm, IPC High Density)
footprint 32MA_M (Thin QFP, 32-Leads, Body 7x7mm, Pitch 0.8mm, IPC Low Density)
pins: 1 PD3 (PCINT19/OC2B/INT1) (io), 2 PD4 (PCINT20/XCK/T0) (io), 3 GND (power), 4 VCC (power), 5 GND (power), 6 VCC (power), 7 PB6 (PCINT6/XTAL1/TOSC1) (io), 8 PB7 (PCINT7/XTAL2/TOSC2) (io), 9 PD5 (PCINT21/OC0B/T1) (io), 10 PD6 (PCINT22/OC0A/AIN0) (io), 11 PD7 (PCINT23/AIN1) (io), 12 PB0 (PCINT0/CLKO/ICP1) (io), 13 PB1 (PCINT1/OC1A) (io), 14 PB2 (PCINT2/~{SS}/OC1B) (io), 15 PB3 (PCINT3/OC2A/MOSI) (io), 16 PB4 (PCINT4/MISO) (io), 17 PB5 (SCK/PCINT5) (io), 18 AVCC (power), 19 ADC6 (in), 20 AREF, 21 GND (power), 22 ADC7 (in), 23 PC0 (ADC0/PCINT8) (io), 24 PC1 (ADC1/PCINT9) (io), 25 PC2 (ADC2/PCINT10) (io), 26 PC3 (ADC3/PCINT11) (io), 27 PC4 (ADC4/SDA/PCINT12) (io), 28 PC5 (ADC5/SCL/PCINT13) (io), 29 PC6 (~{RESET}/PCINT14) (io), 30 PD0 (RXD/PCINT16) (io), 31 PD1 (TXD/PCINT17) (io), 32 PD2 (INT0/PCINT18) (io)

## ATmega168-15AT1
designator U?
8-bit Automotive AVR Microcontroller, 16KB Flash, 512 Bytes EEPROM, 1KB SRAM, Automotive Grade (-40°C to +105°C), 32-Pin TQFP
footprint 32MA_N (Thin QFP, 32-Leads, Body 7x7mm, Pitch 0.8mm, IPC Medium Density)
footprint 32MA_L (Thin QFP, 32-Leads, Body 7x7mm, Pitch 0.8mm, IPC High Density)
footprint 32MA_M (Thin QFP, 32-Leads, Body 7x7mm, Pitch 0.8mm, IPC Low Density)
pins: 1 PD3 (PCINT19/OC2B/INT1) (io), 2 PD4 (PCINT20/XCK/T0) (io), 3 GND (power), 4 VCC (power), 5 GND (power), 6 VCC (power), 7 PB6 (PCINT6/XTAL1/TOSC1) (io), 8 PB7 (PCINT7/XTAL2/TOSC2) (io), 9 PD5 (PCINT21/OC0B/T1) (io), 10 PD6 (PCINT22/OC0A/AIN0) (io), 11 PD7 (PCINT23/AIN1) (io), 12 PB0 (PCINT0/CLKO/ICP1) (io), 13 PB1 (PCINT1/OC1A) (io), 14 PB2 (PCINT2/~{SS}/OC1B) (io), 15 PB3 (PCINT3/OC2A/MOSI) (io), 16 PB4 (PCINT4/MISO) (io), 17 PB5 (SCK/PCINT5) (io), 18 AVCC (power), 19 ADC6 (in), 20 AREF, 21 GND (power), 22 ADC7 (in), 23 PC0 (ADC0/PCINT8) (io), 24 PC1 (ADC1/PCINT9) (io), 25 PC2 (ADC2/PCINT10) (io), 26 PC3 (ADC3/PCINT11) (io), 27 PC4 (ADC4/SDA/PCINT12) (io), 28 PC5 (ADC5/SCL/PCINT13) (io), 29 PC6 (~{RESET}/PCINT14) (io), 30 PD0 (RXD/PCINT16) (io), 31 PD1 (TXD/PCINT17) (io), 32 PD2 (INT0/PCINT18) (io)

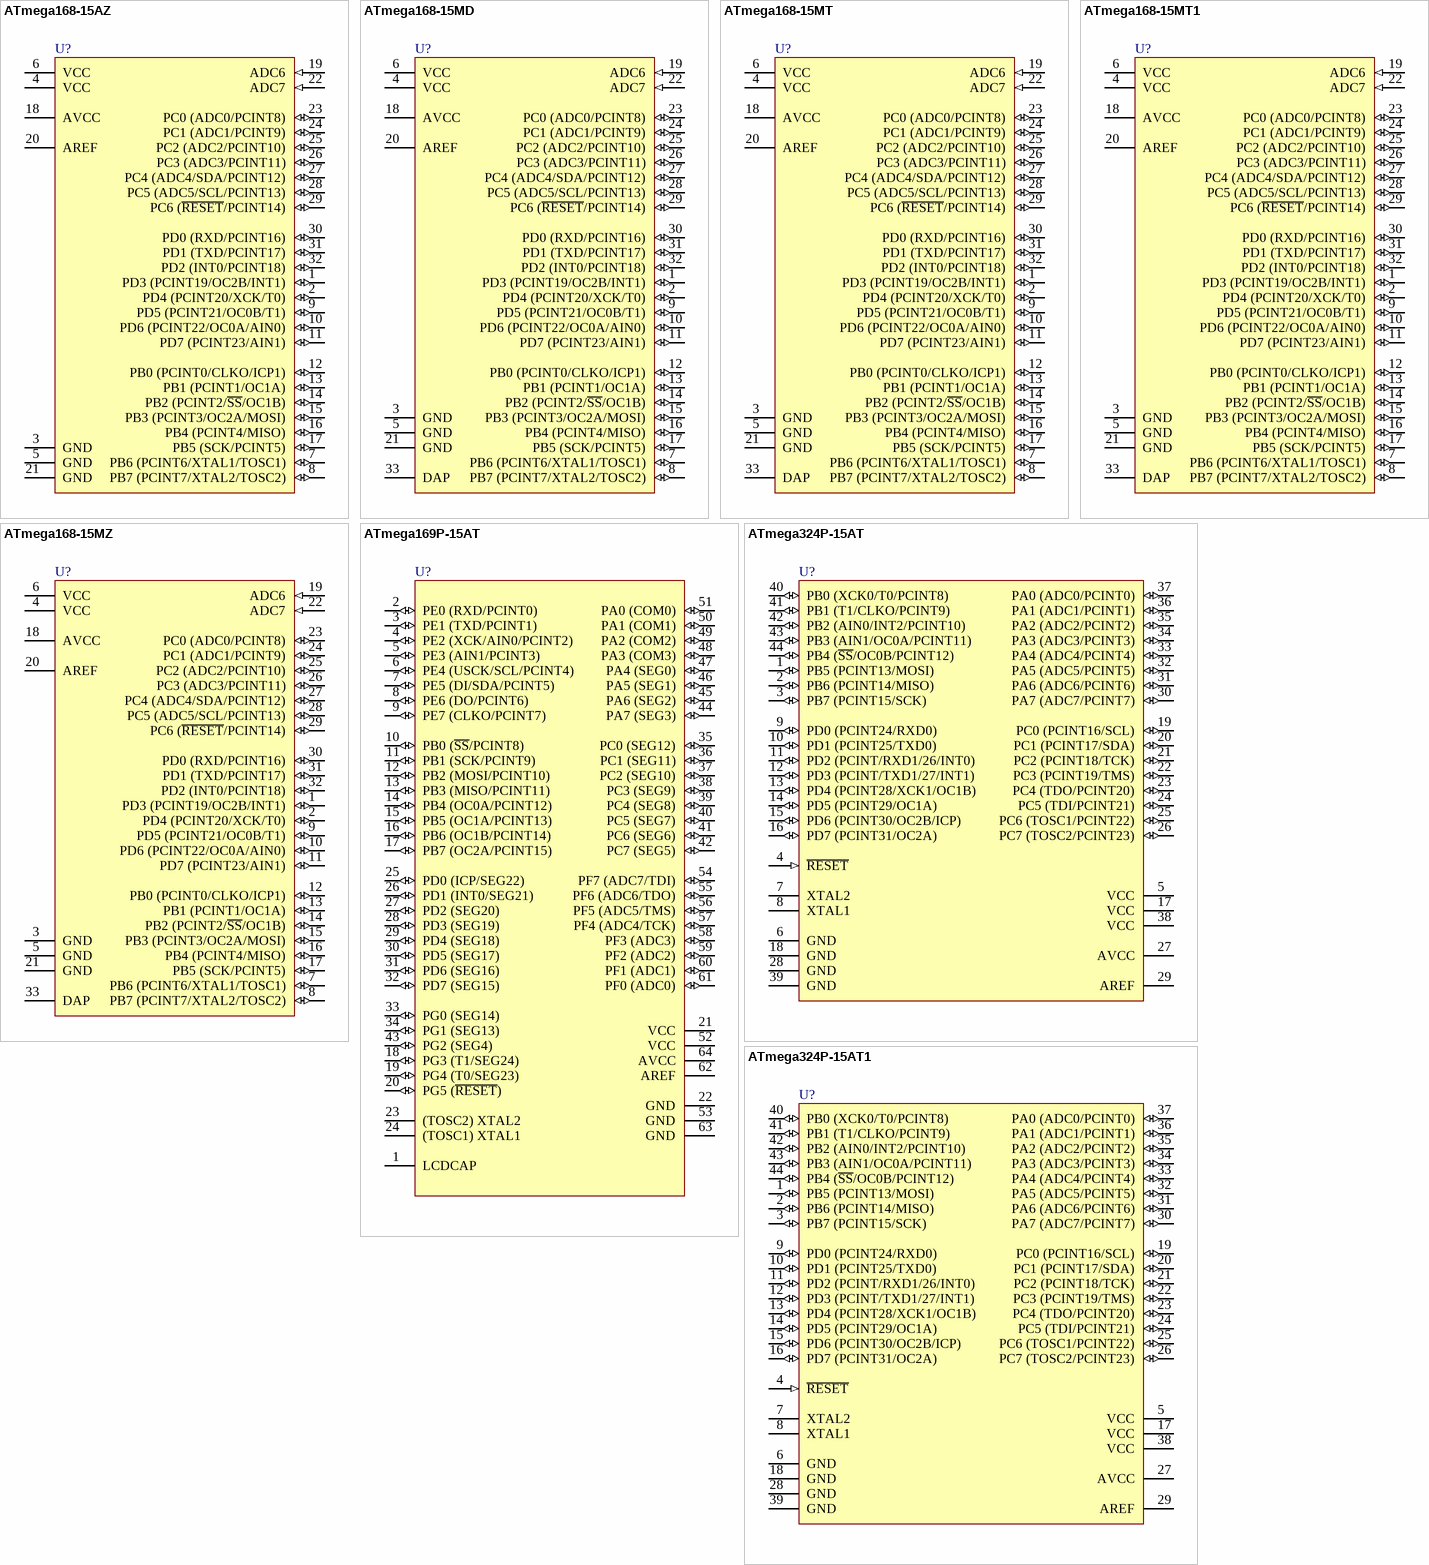
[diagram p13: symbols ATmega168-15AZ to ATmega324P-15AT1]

## ATmega168-15AZ
designator U?
8-bit Automotive AVR Microcontroller, 16KB Flash, 512 Bytes EEPROM, 1KB SRAM, Automotive Grade (-40°C to +125°C), 32-Pin TQFP
footprint 32MA_N (Thin QFP, 32-Leads, Body 7x7mm, Pitch 0.8mm, IPC Medium Density)
footprint 32MA_L (Thin QFP, 32-Leads, Body 7x7mm, Pitch 0.8mm, IPC High Density)
footprint 32MA_M (Thin QFP, 32-Leads, Body 7x7mm, Pitch 0.8mm, IPC Low Density)
pins: 1 PD3 (PCINT19/OC2B/INT1) (io), 2 PD4 (PCINT20/XCK/T0) (io), 3 GND (power), 4 VCC (power), 5 GND (power), 6 VCC (power), 7 PB6 (PCINT6/XTAL1/TOSC1) (io), 8 PB7 (PCINT7/XTAL2/TOSC2) (io), 9 PD5 (PCINT21/OC0B/T1) (io), 10 PD6 (PCINT22/OC0A/AIN0) (io), 11 PD7 (PCINT23/AIN1) (io), 12 PB0 (PCINT0/CLKO/ICP1) (io), 13 PB1 (PCINT1/OC1A) (io), 14 PB2 (PCINT2/~{SS}/OC1B) (io), 15 PB3 (PCINT3/OC2A/MOSI) (io), 16 PB4 (PCINT4/MISO) (io), 17 PB5 (SCK/PCINT5) (io), 18 AVCC (power), 19 ADC6 (in), 20 AREF, 21 GND (power), 22 ADC7 (in), 23 PC0 (ADC0/PCINT8) (io), 24 PC1 (ADC1/PCINT9) (io), 25 PC2 (ADC2/PCINT10) (io), 26 PC3 (ADC3/PCINT11) (io), 27 PC4 (ADC4/SDA/PCINT12) (io), 28 PC5 (ADC5/SCL/PCINT13) (io), 29 PC6 (~{RESET}/PCINT14) (io), 30 PD0 (RXD/PCINT16) (io), 31 PD1 (TXD/PCINT17) (io), 32 PD2 (INT0/PCINT18) (io)

## ATmega168-15MD
designator U?
8-bit Automotive AVR Microcontroller, 16KB Flash, 512 Bytes EEPROM, 1KB SRAM, Extended Grade (-40°C to +150°C), 32-Pin VQFN
footprint 32PN_N (QFN, 32-Leads, Body 5x5mm, Pitch 0.5mm, IPC Medium Density)
footprint 32PN_L (QFN, 32-Leads, Body 5x5mm, Pitch 0.5mm, IPC High Density)
footprint 32PN_M (QFN, 32-Leads, Body 5x5mm, Pitch 0.5mm, IPC Low Density)
pins: 1 PD3 (PCINT19/OC2B/INT1) (io), 2 PD4 (PCINT20/XCK/T0) (io), 3 GND (power), 4 VCC (power), 5 GND (power), 6 VCC (power), 7 PB6 (PCINT6/XTAL1/TOSC1) (io), 8 PB7 (PCINT7/XTAL2/TOSC2) (io), 9 PD5 (PCINT21/OC0B/T1) (io), 10 PD6 (PCINT22/OC0A/AIN0) (io), 11 PD7 (PCINT23/AIN1) (io), 12 PB0 (PCINT0/CLKO/ICP1) (io), 13 PB1 (PCINT1/OC1A) (io), 14 PB2 (PCINT2/~{SS}/OC1B) (io), 15 PB3 (PCINT3/OC2A/MOSI) (io), 16 PB4 (PCINT4/MISO) (io), 17 PB5 (SCK/PCINT5) (io), 18 AVCC (power), 19 ADC6 (in), 20 AREF, 21 GND (power), 22 ADC7 (in), 23 PC0 (ADC0/PCINT8) (io), 24 PC1 (ADC1/PCINT9) (io), 25 PC2 (ADC2/PCINT10) (io), 26 PC3 (ADC3/PCINT11) (io), 27 PC4 (ADC4/SDA/PCINT12) (io), 28 PC5 (ADC5/SCL/PCINT13) (io), 29 PC6 (~{RESET}/PCINT14) (io), 30 PD0 (RXD/PCINT16) (io), 31 PD1 (TXD/PCINT17) (io), 32 PD2 (INT0/PCINT18) (io), 33 DAP (power)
